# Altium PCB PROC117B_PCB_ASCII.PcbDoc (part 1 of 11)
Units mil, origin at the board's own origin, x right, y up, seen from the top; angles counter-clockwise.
Board outline 2480.32 x 3185.25 mil, 8 copper layers (Top Layer, L2_GND1, L3_SIG1, L4_PWR1, L5_PWR2, L6_SIG2, L7_GND2, Bottom Layer), stack 57.4 mil thick; 456 components, 292 nets, 7831 pads, 2905 vias.
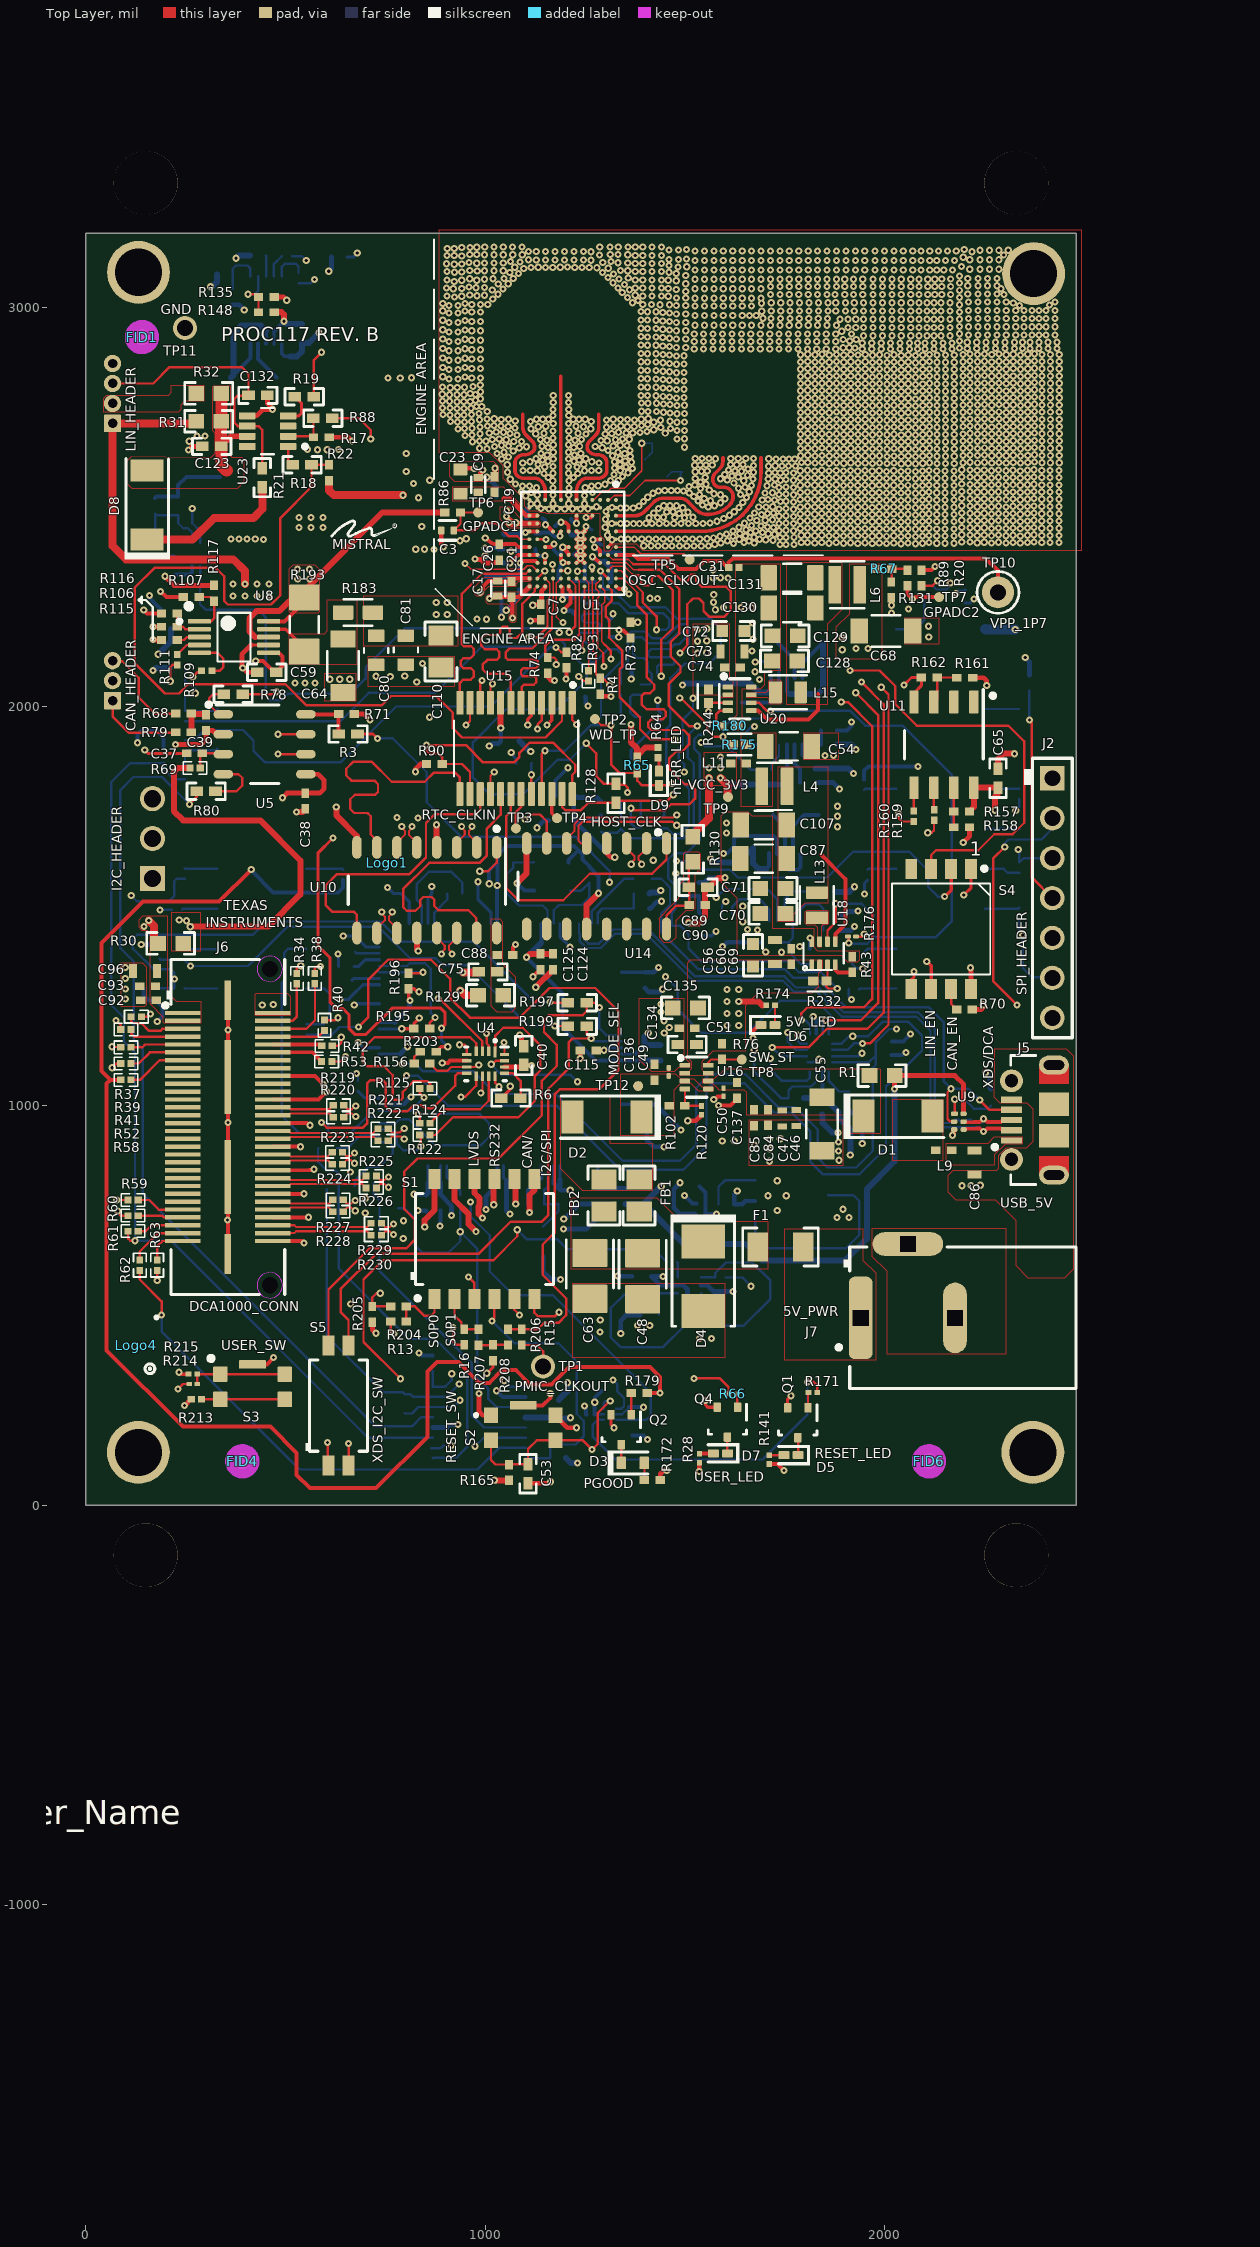
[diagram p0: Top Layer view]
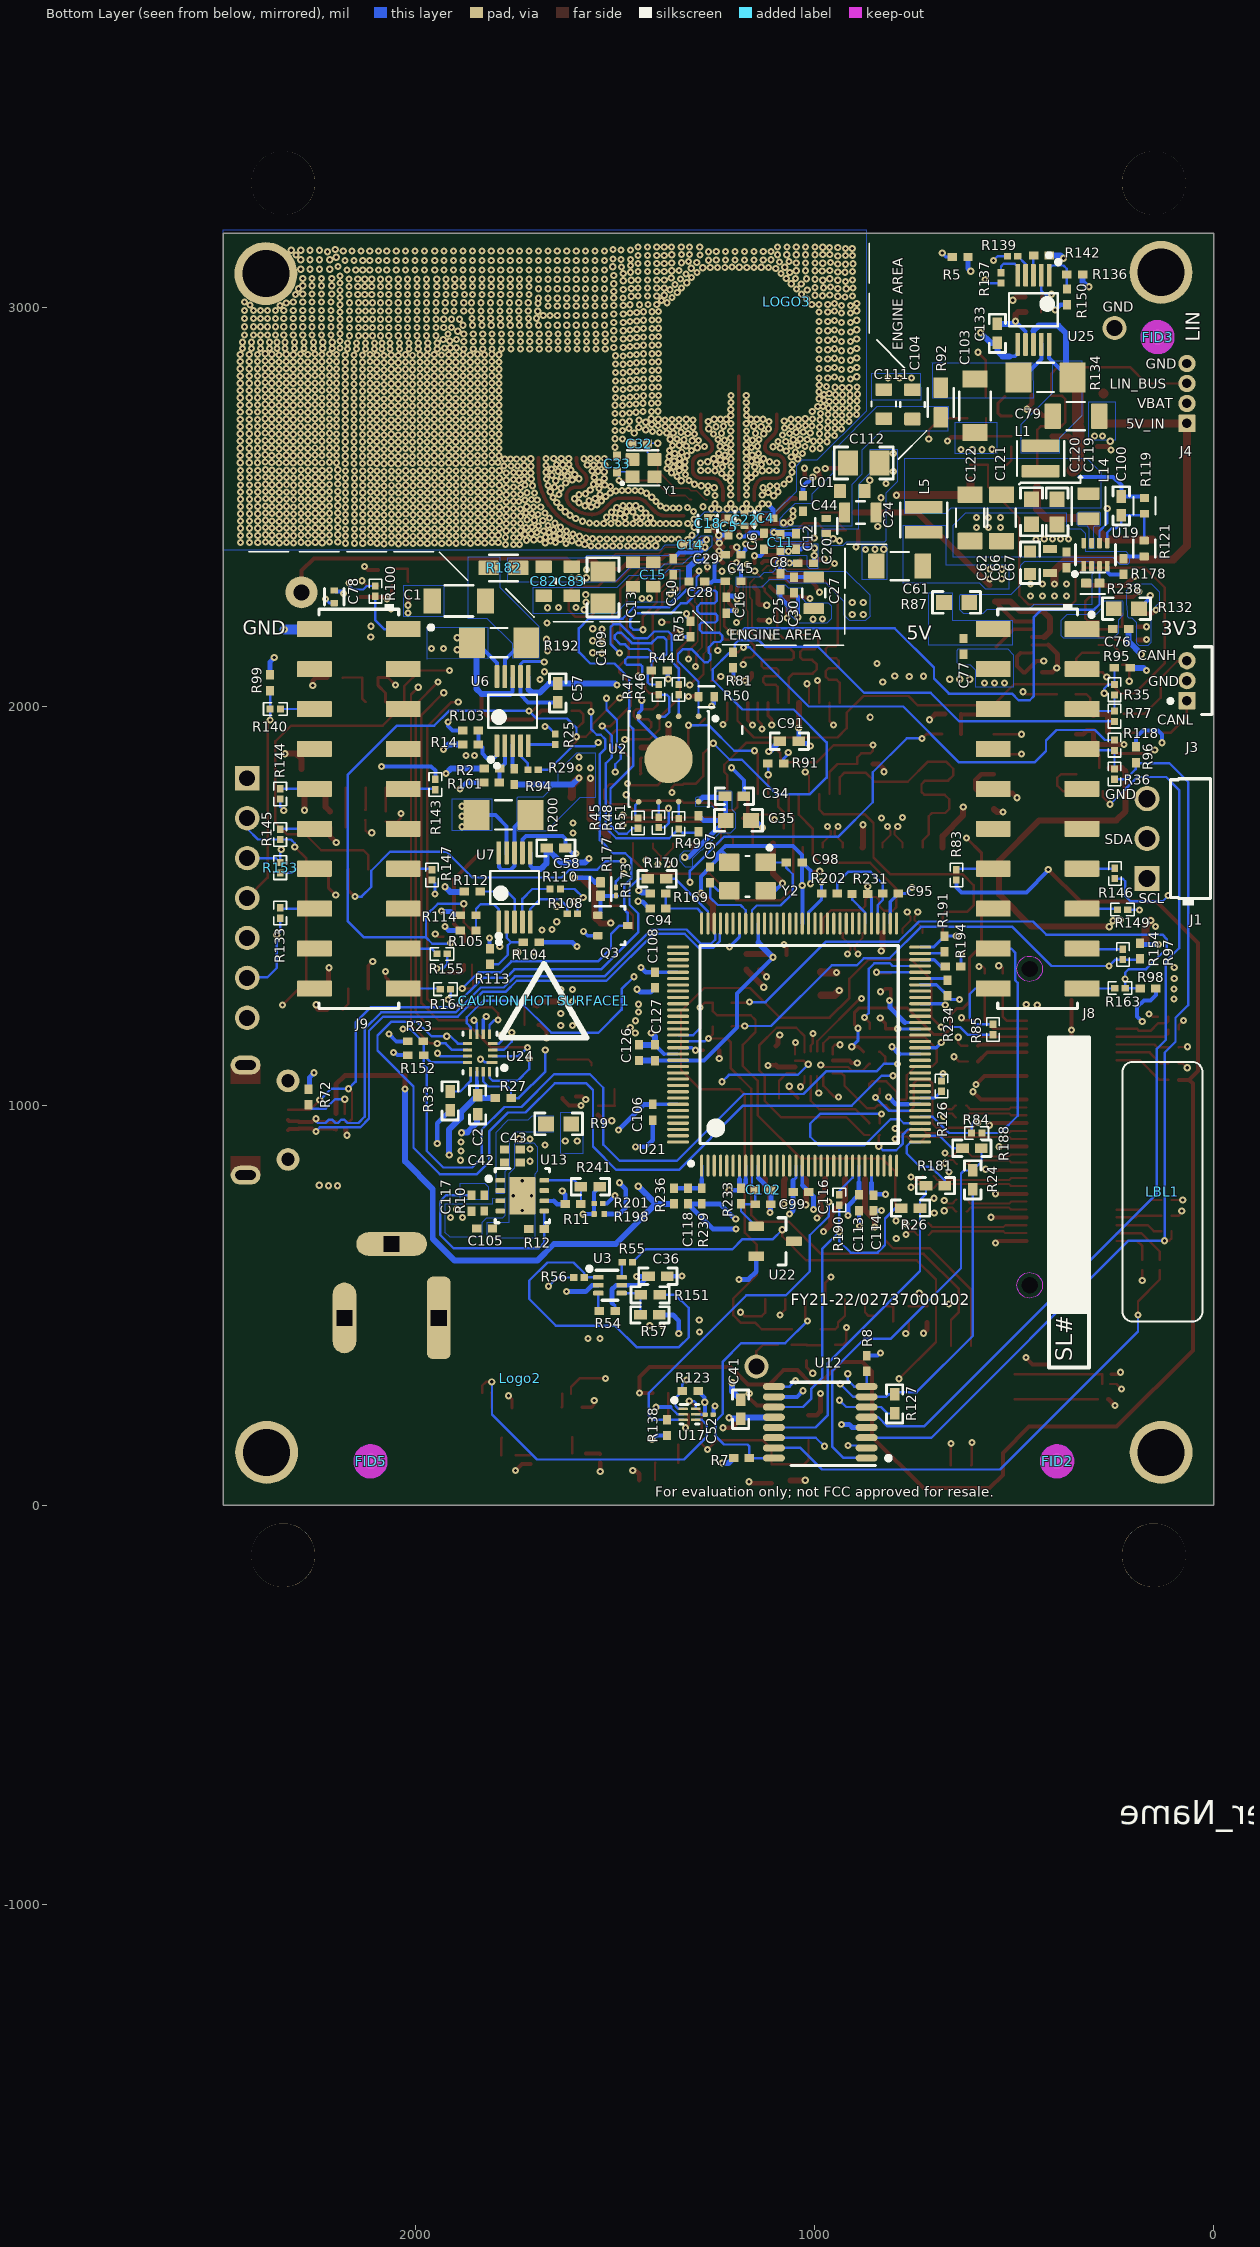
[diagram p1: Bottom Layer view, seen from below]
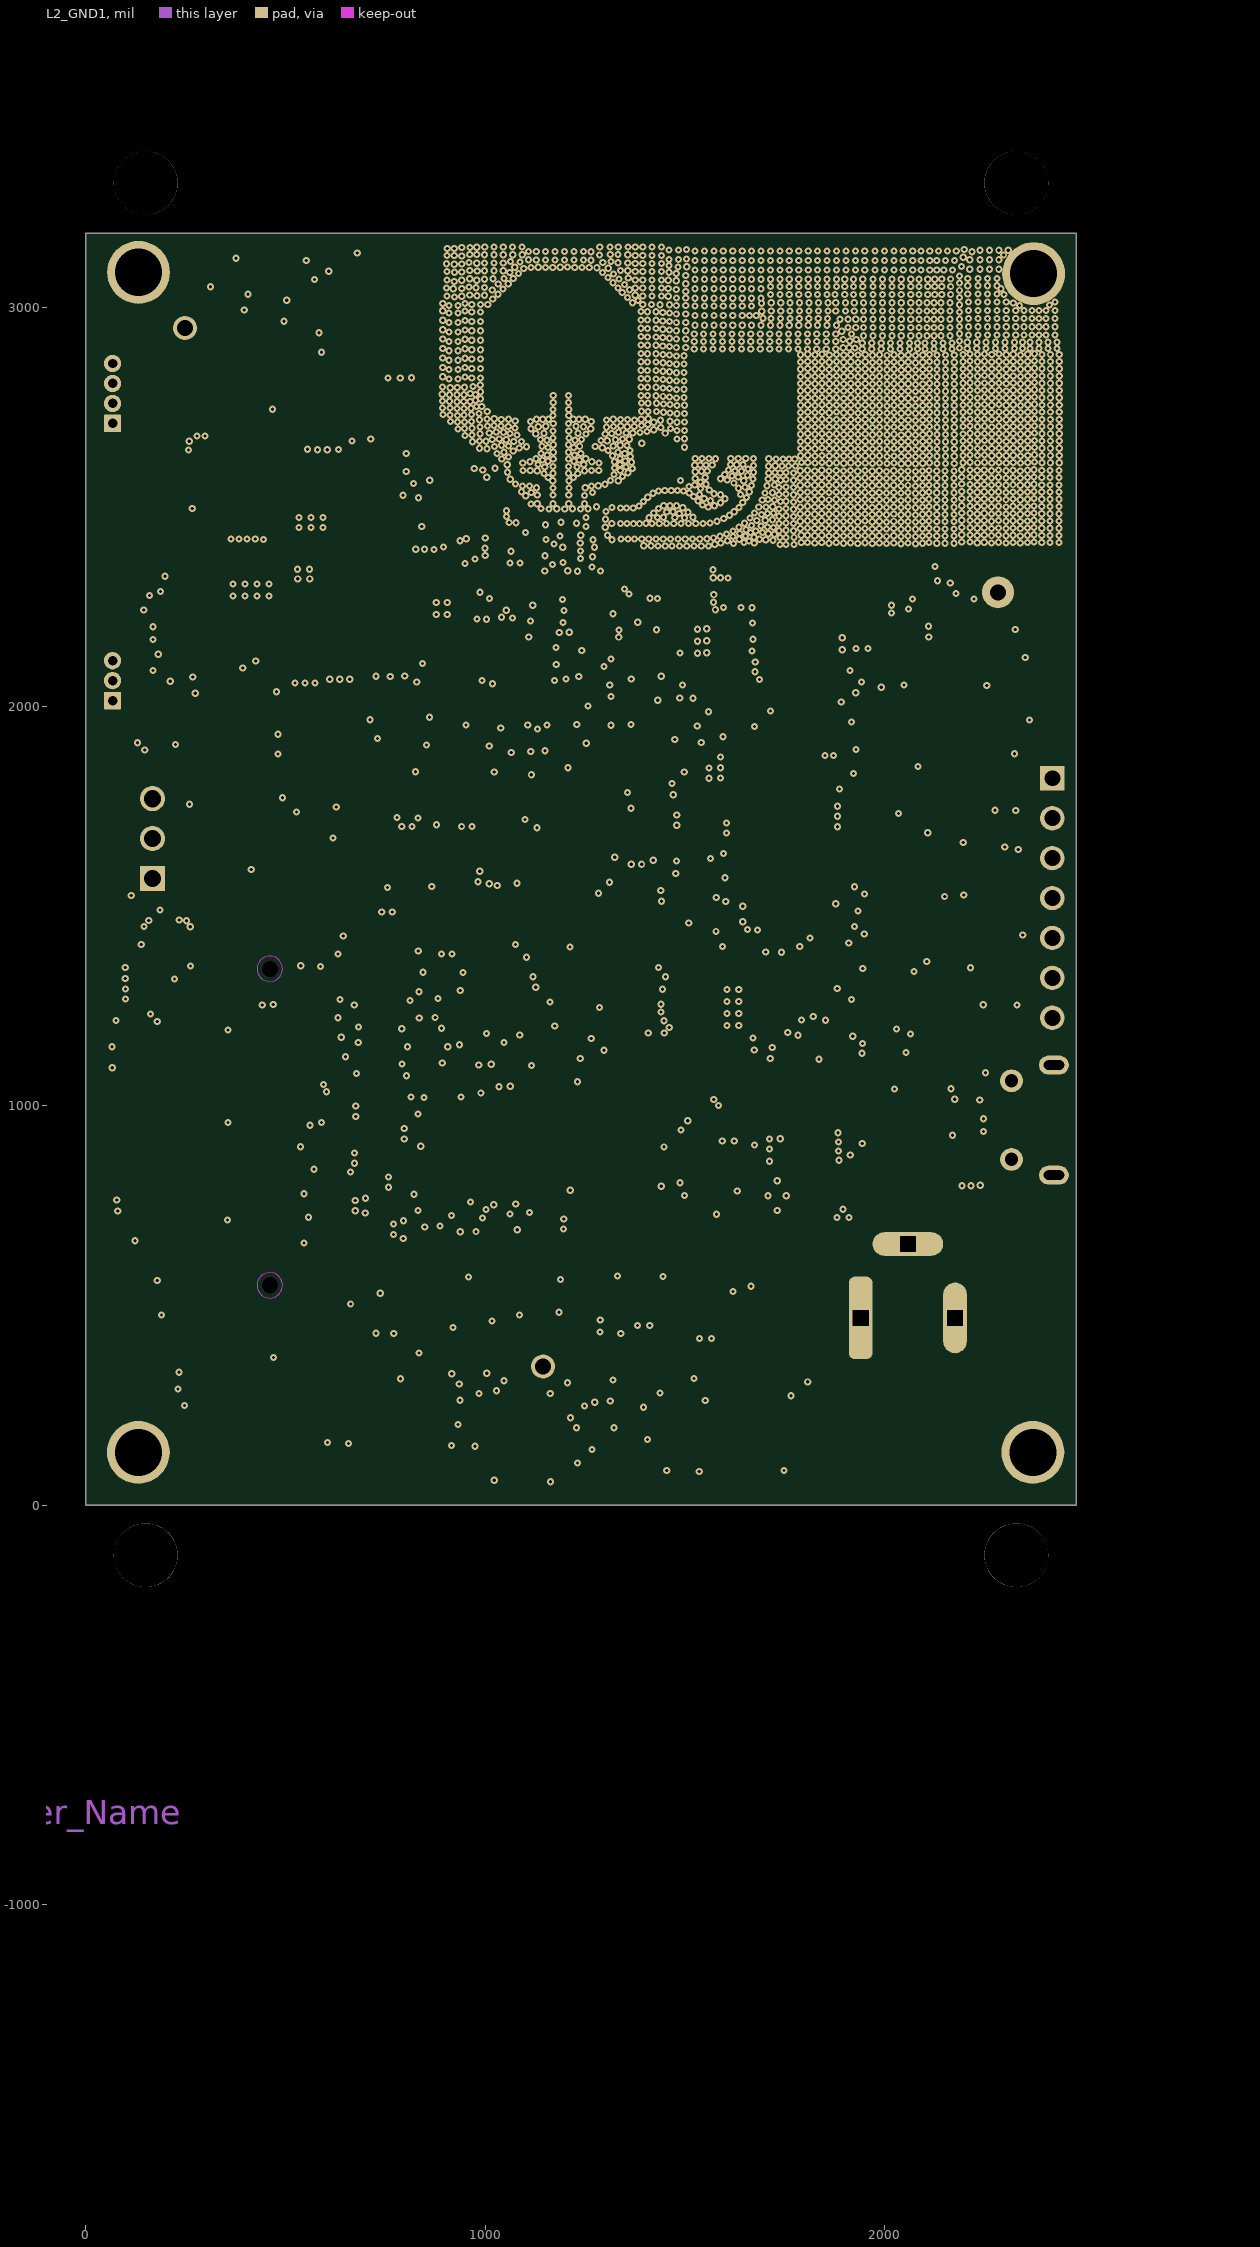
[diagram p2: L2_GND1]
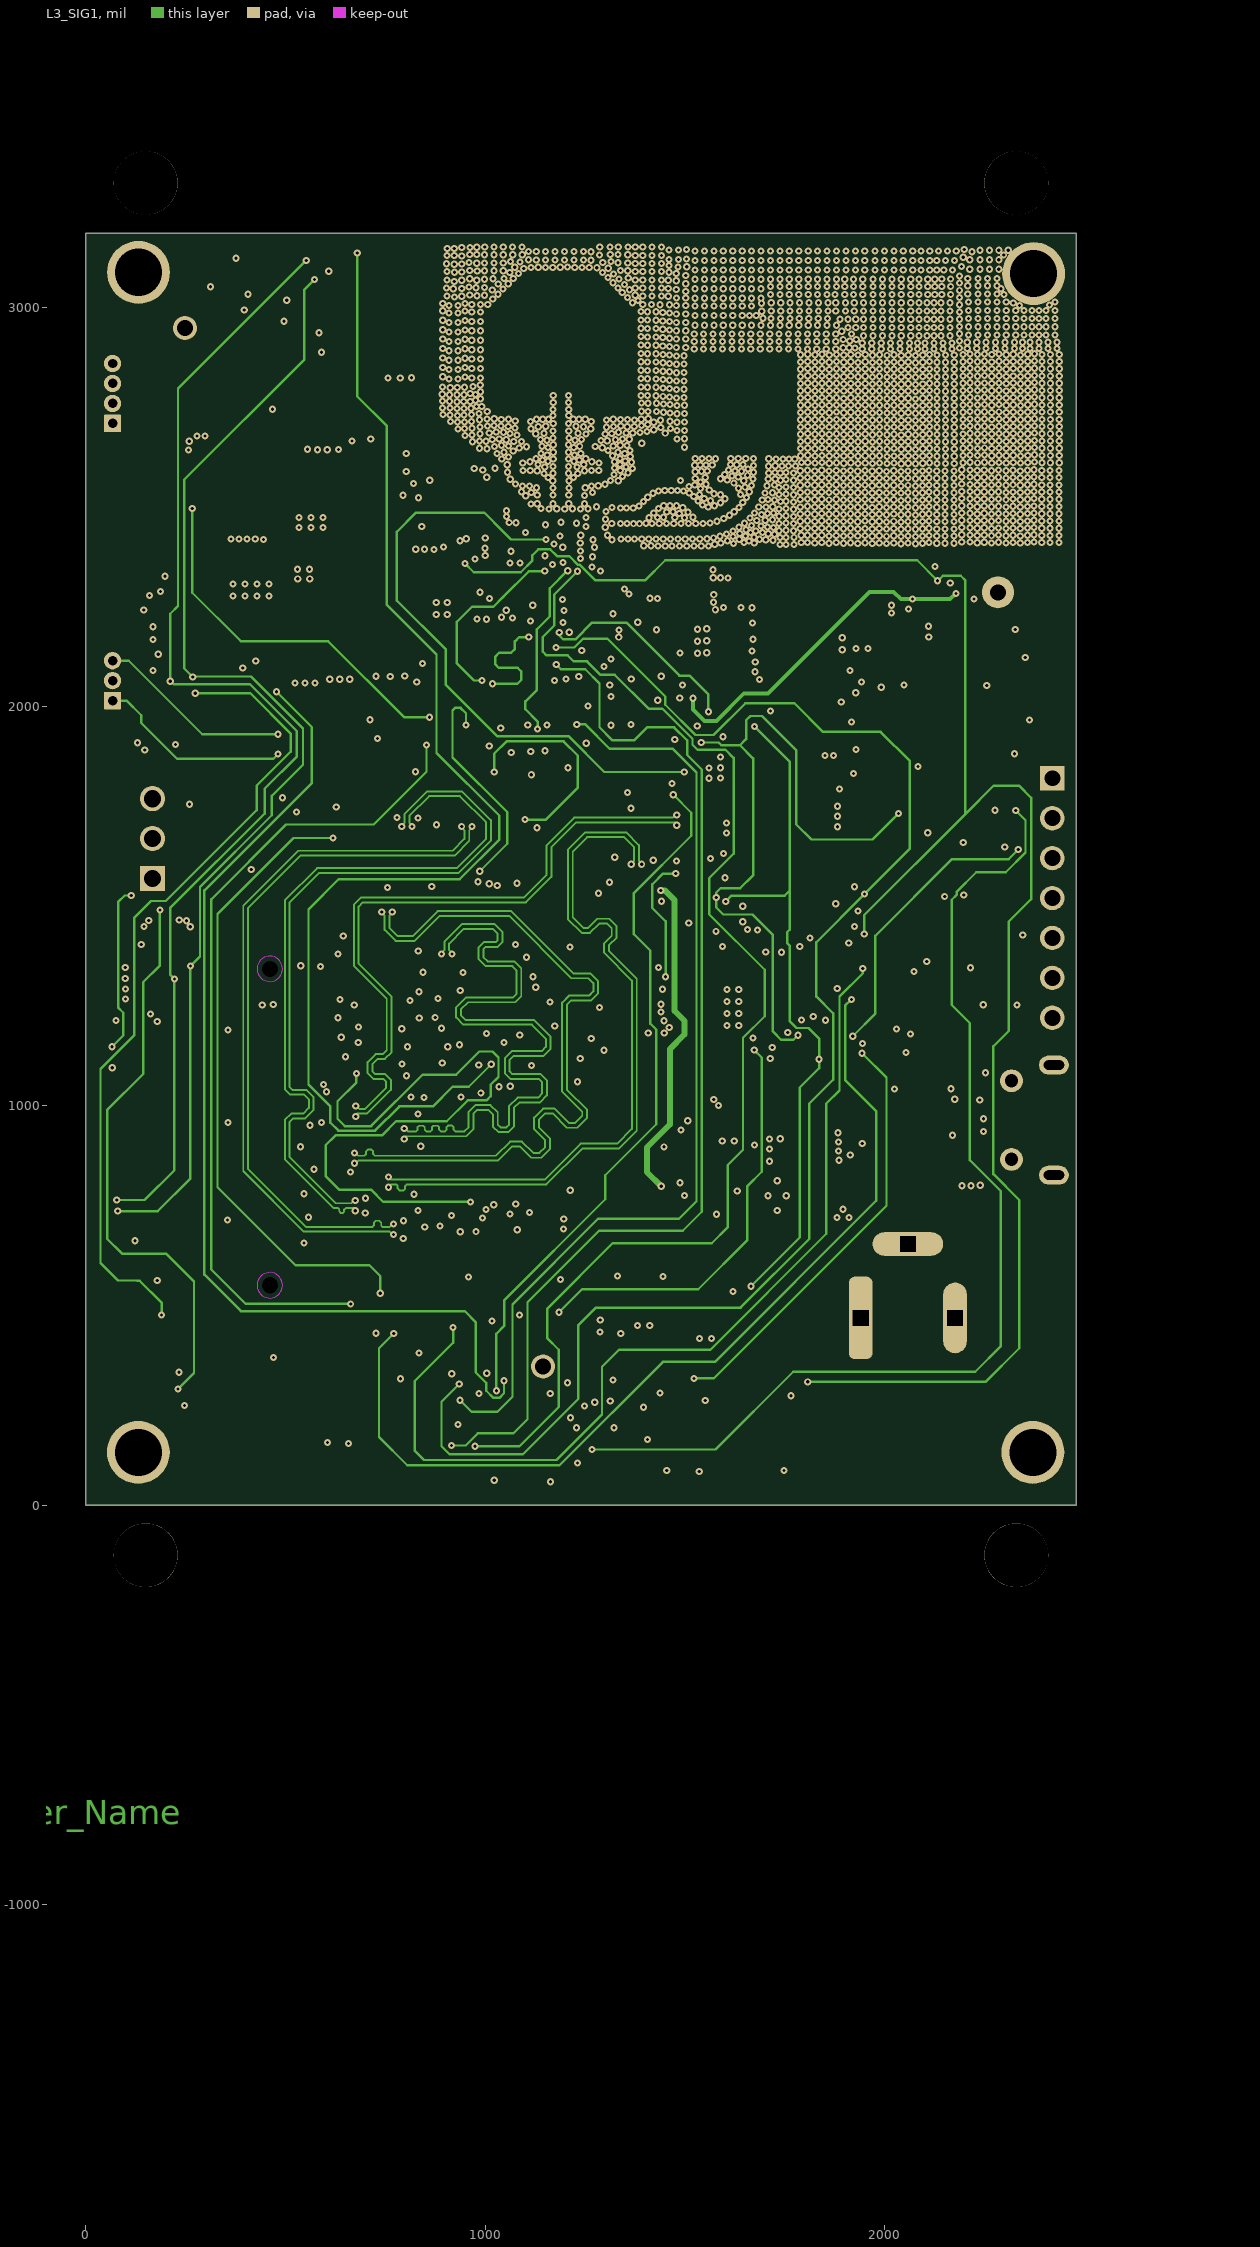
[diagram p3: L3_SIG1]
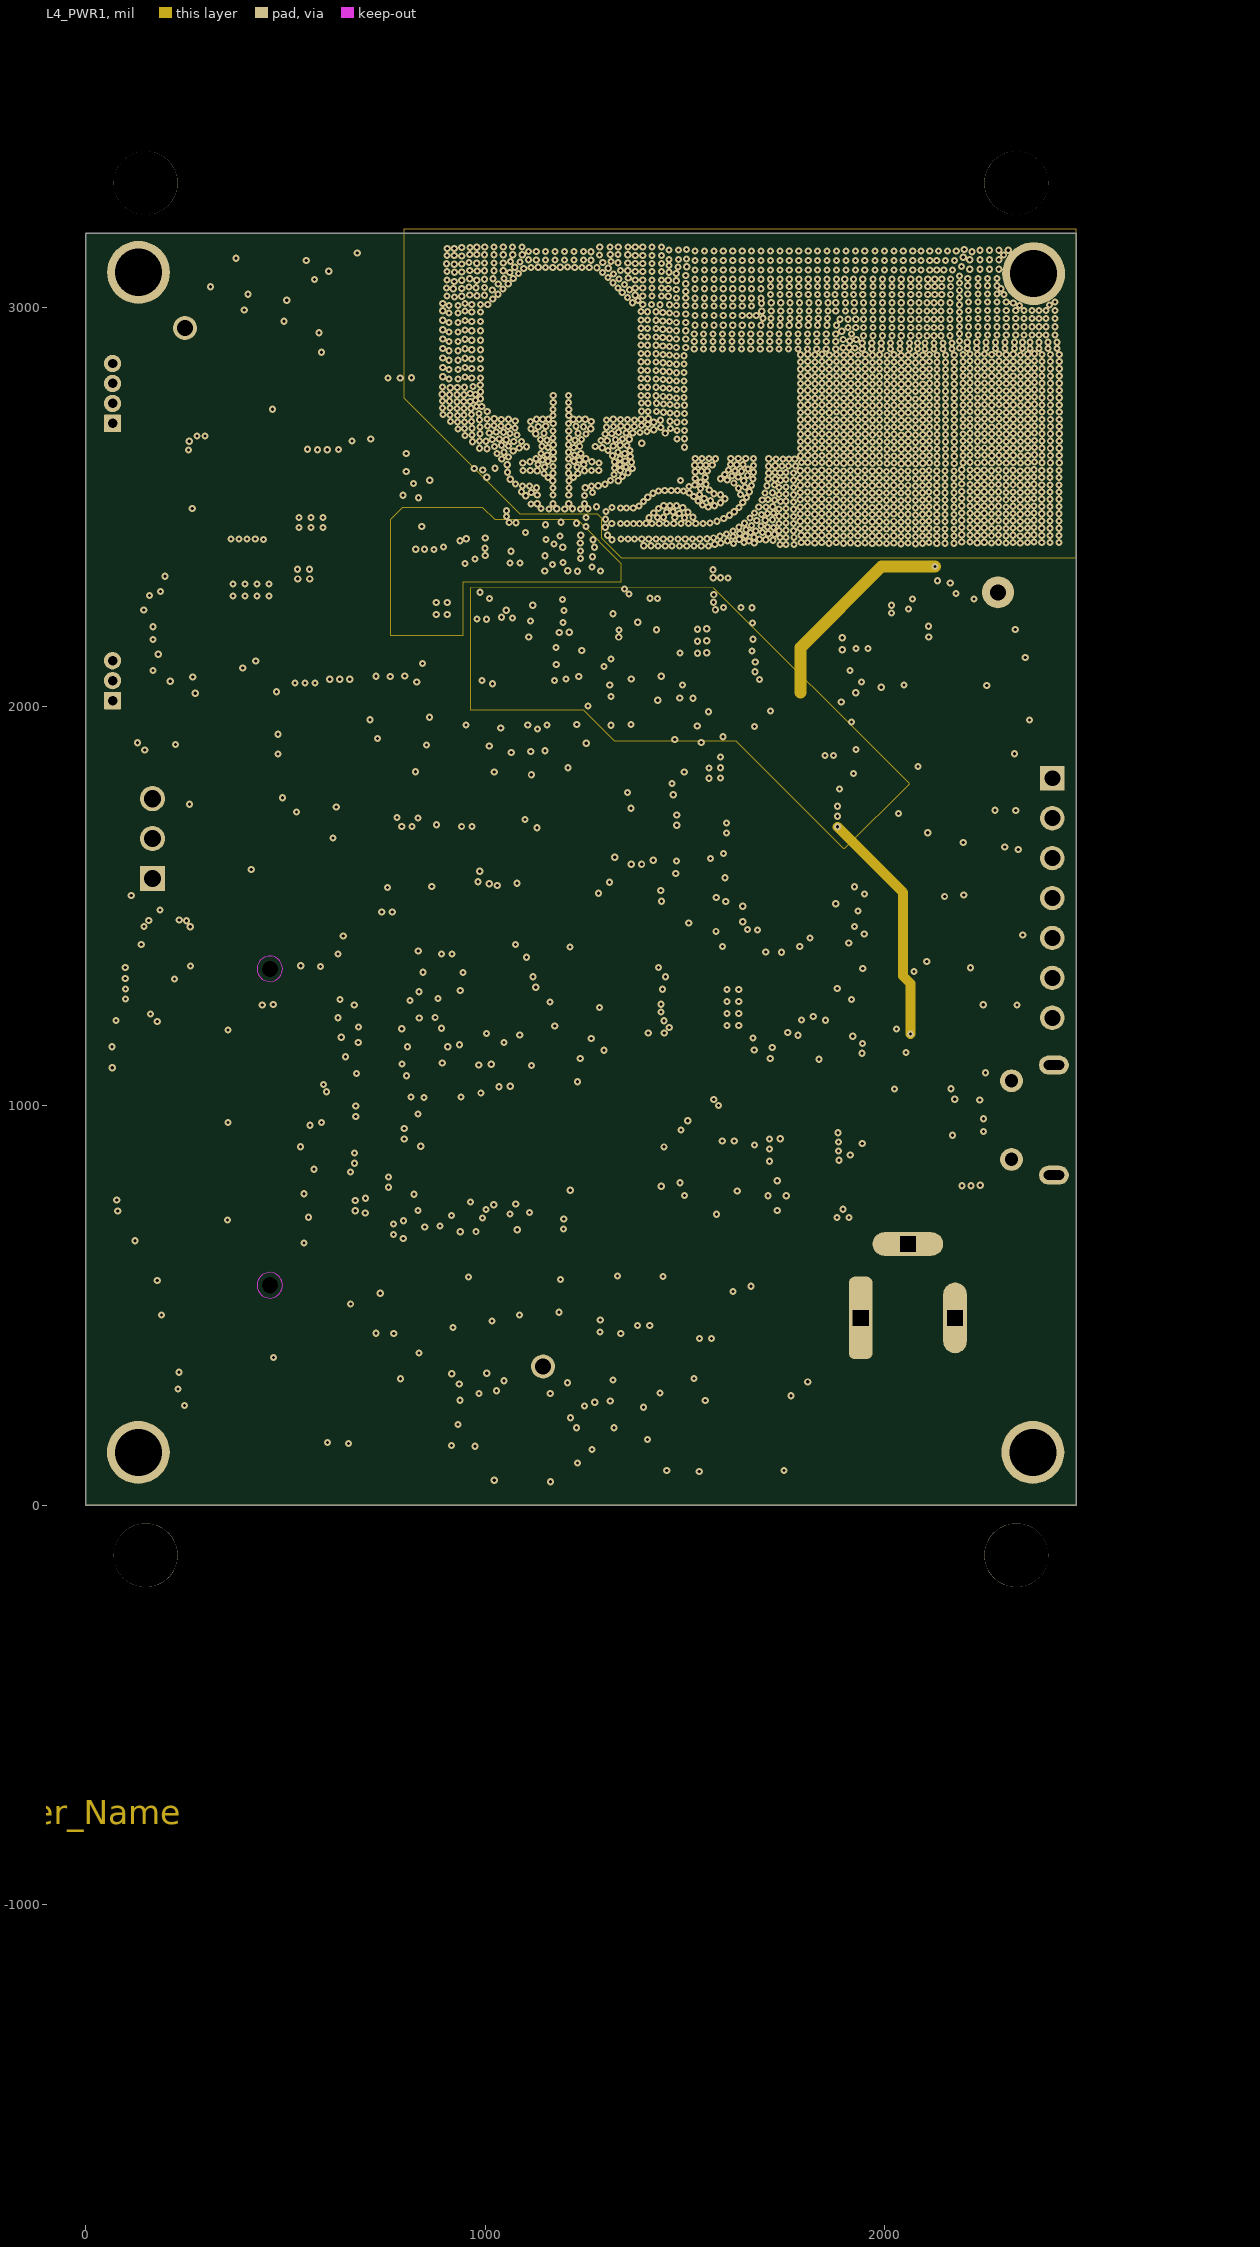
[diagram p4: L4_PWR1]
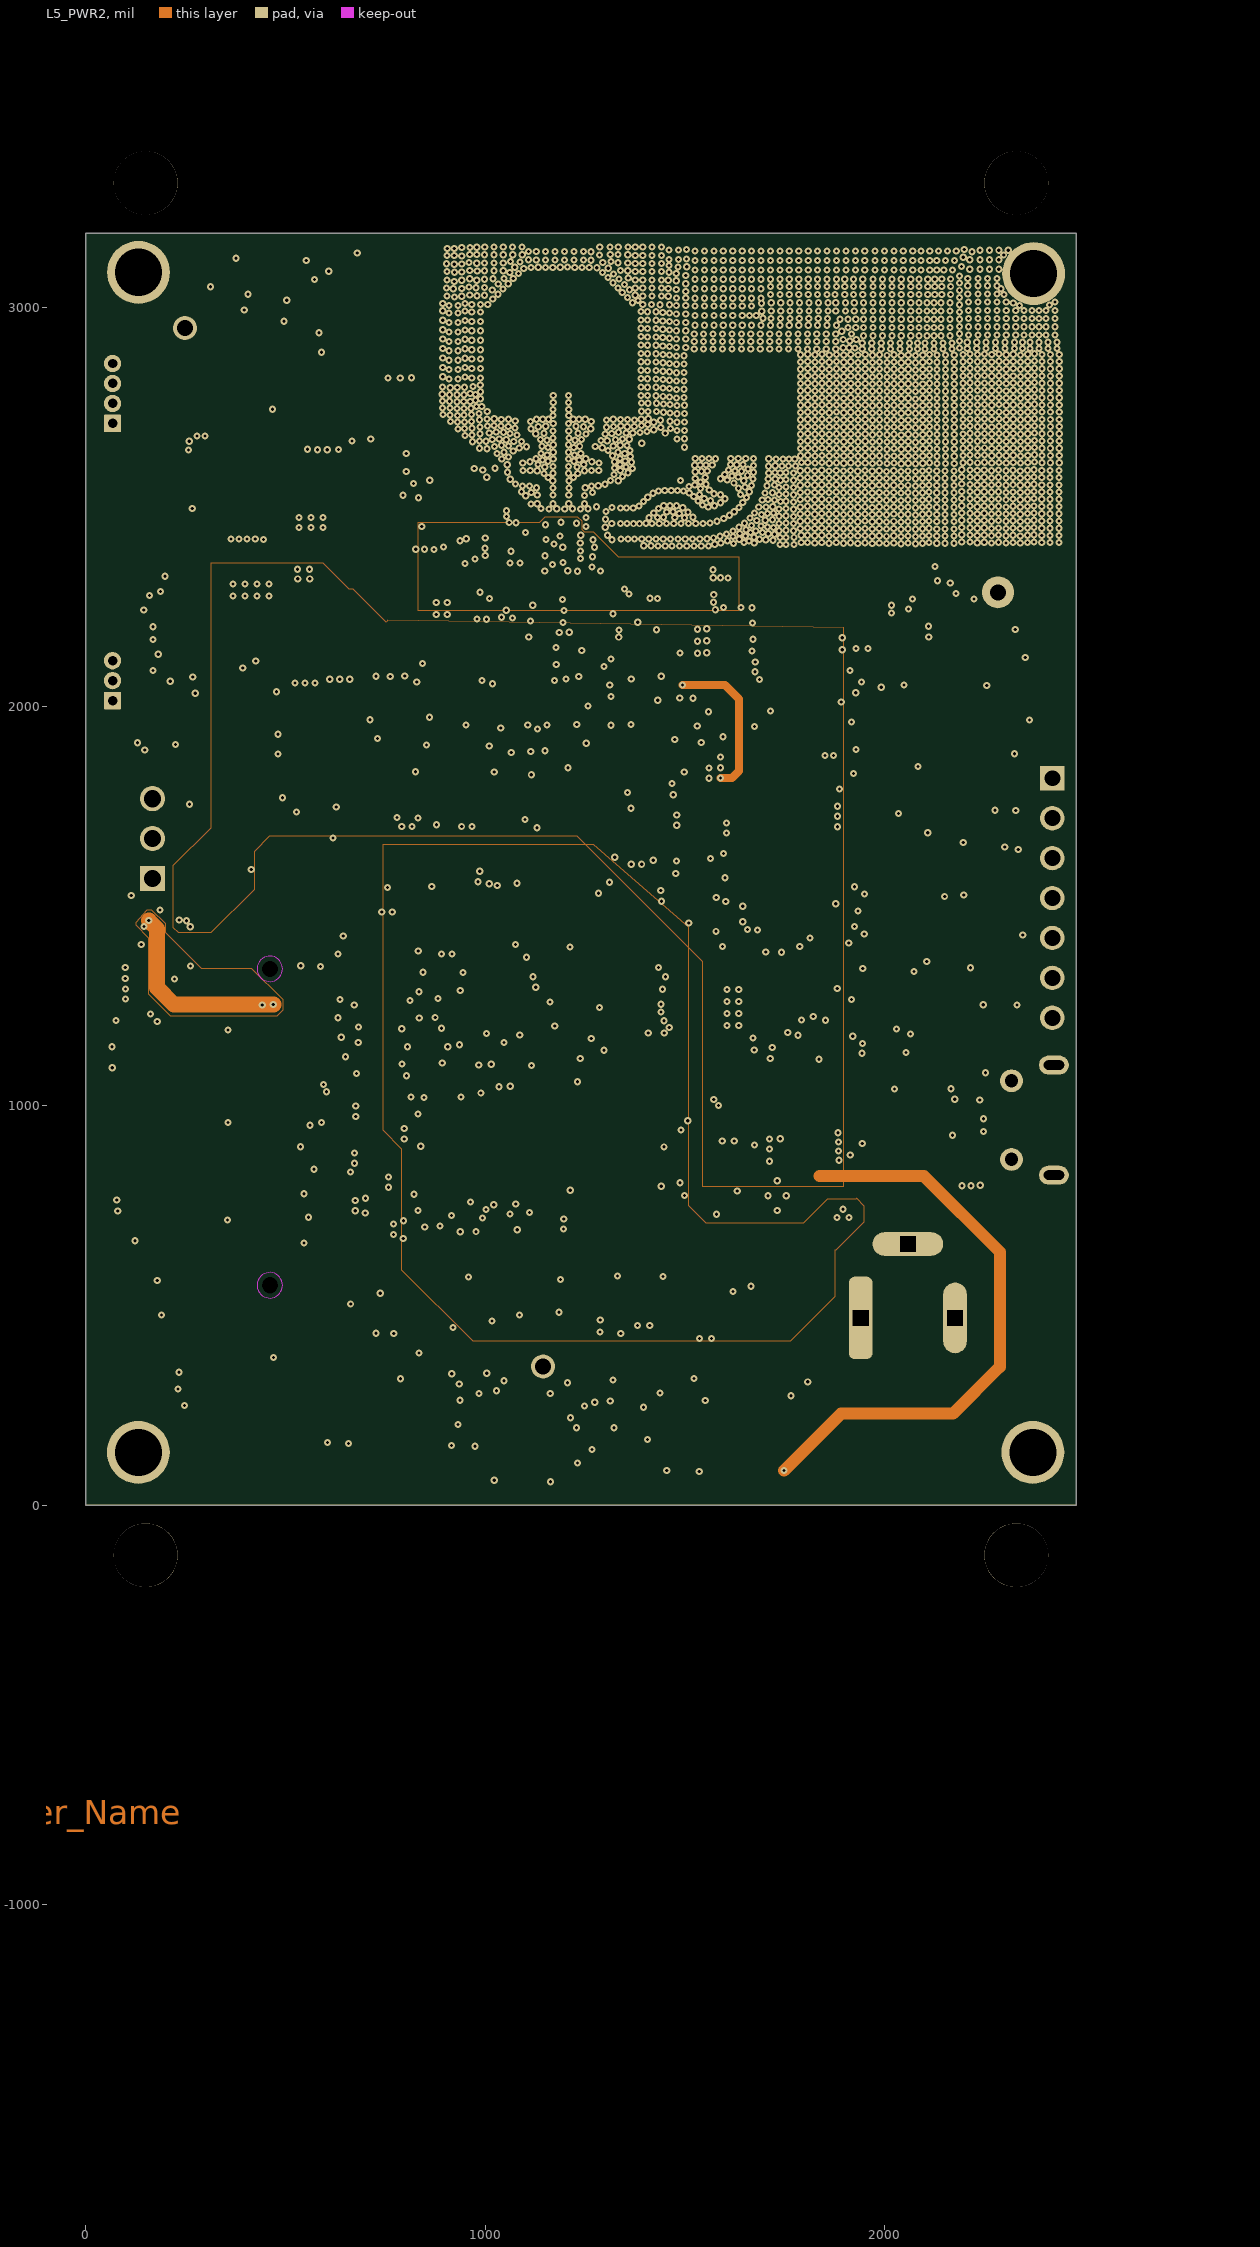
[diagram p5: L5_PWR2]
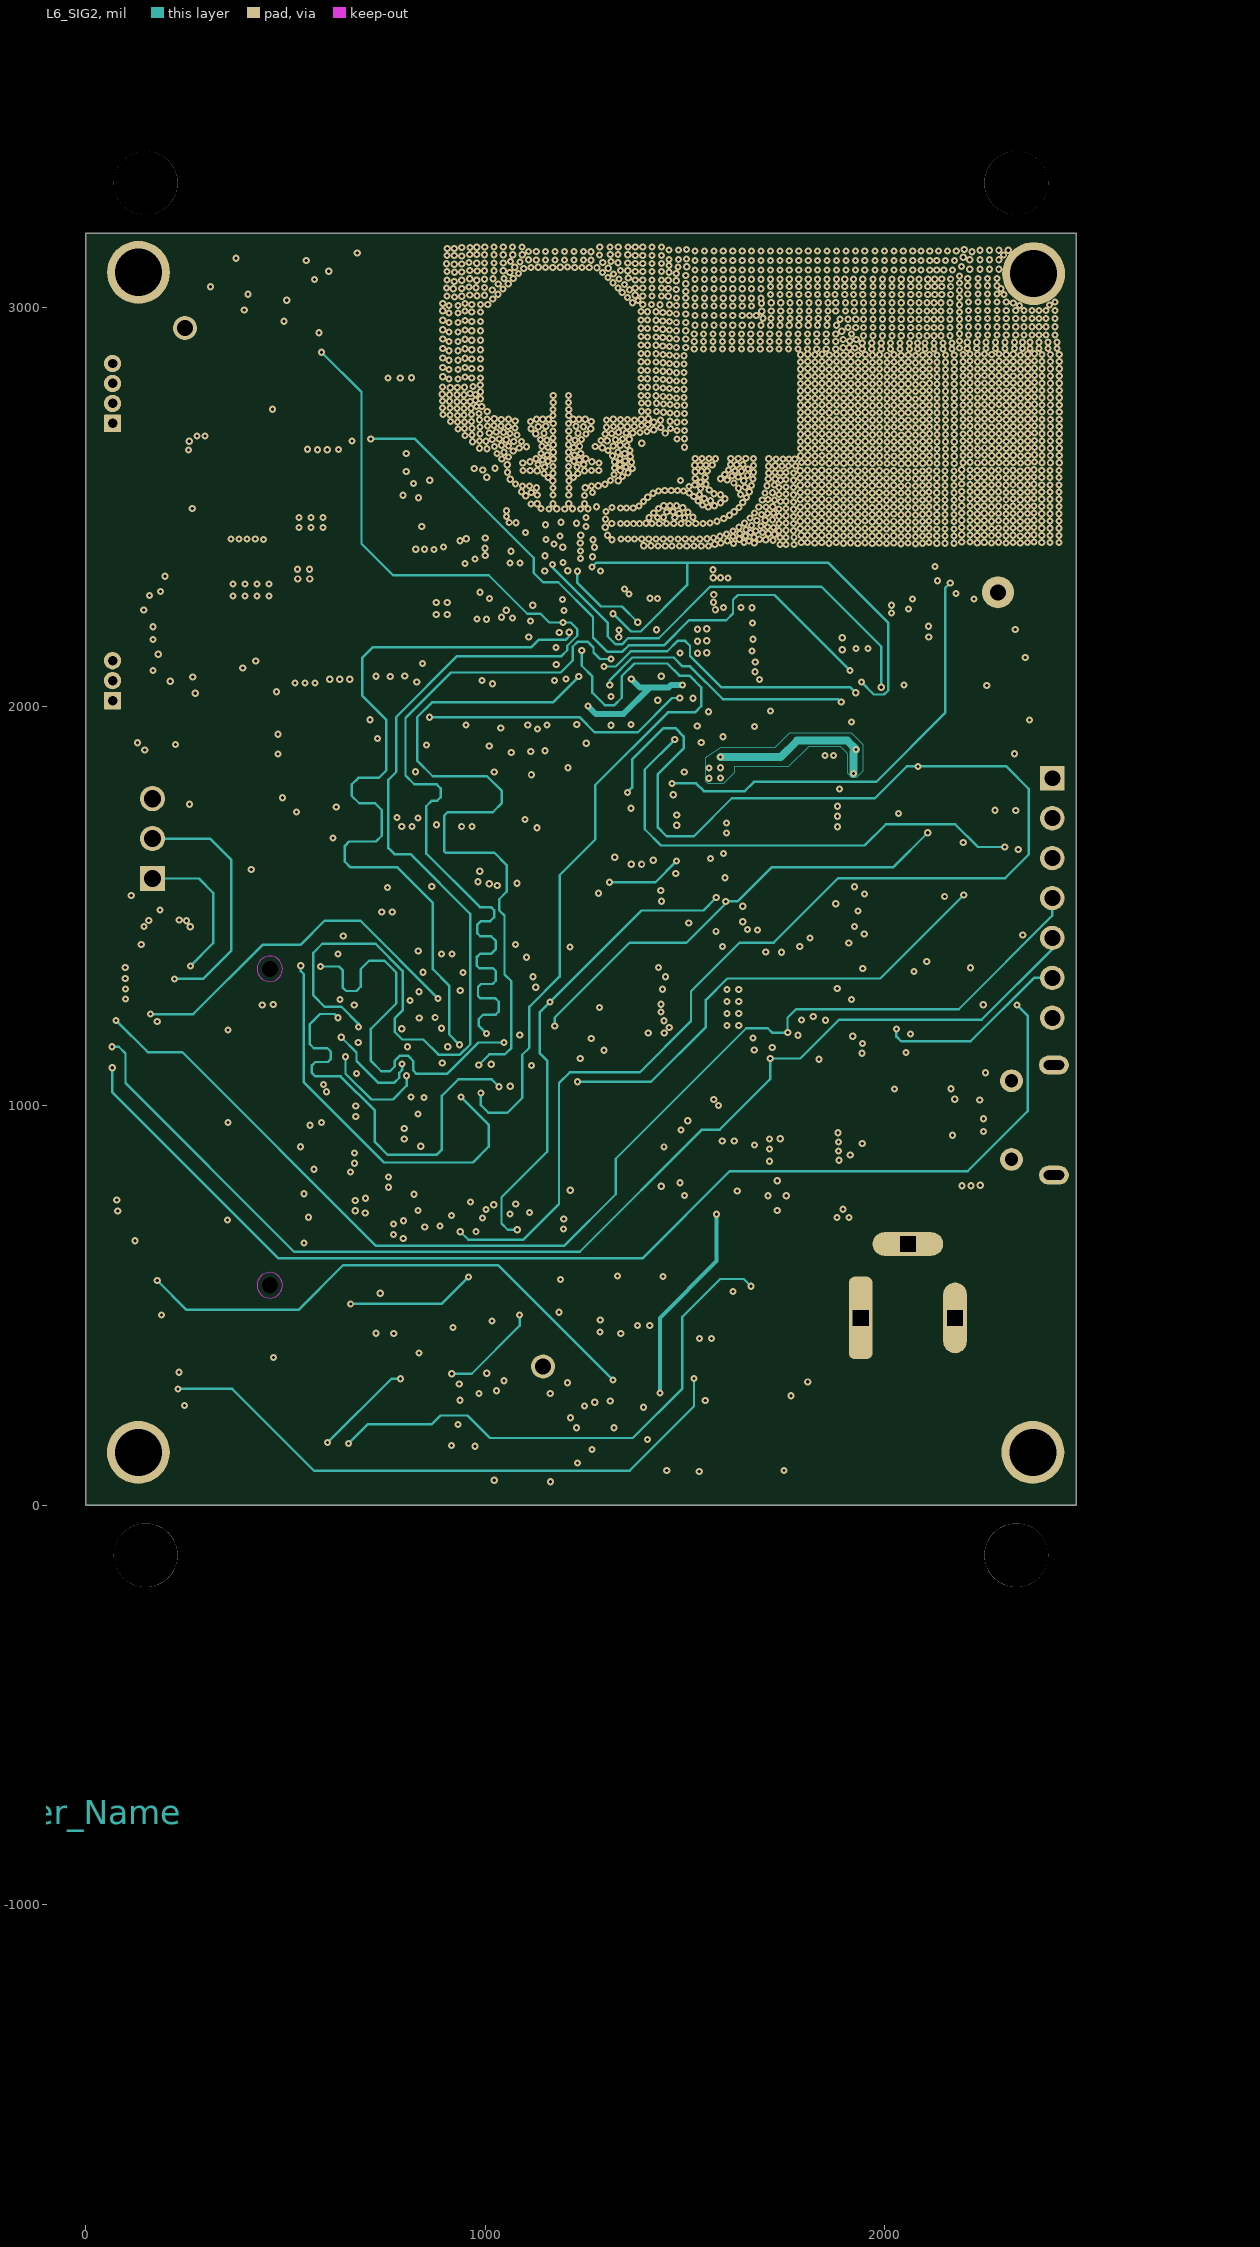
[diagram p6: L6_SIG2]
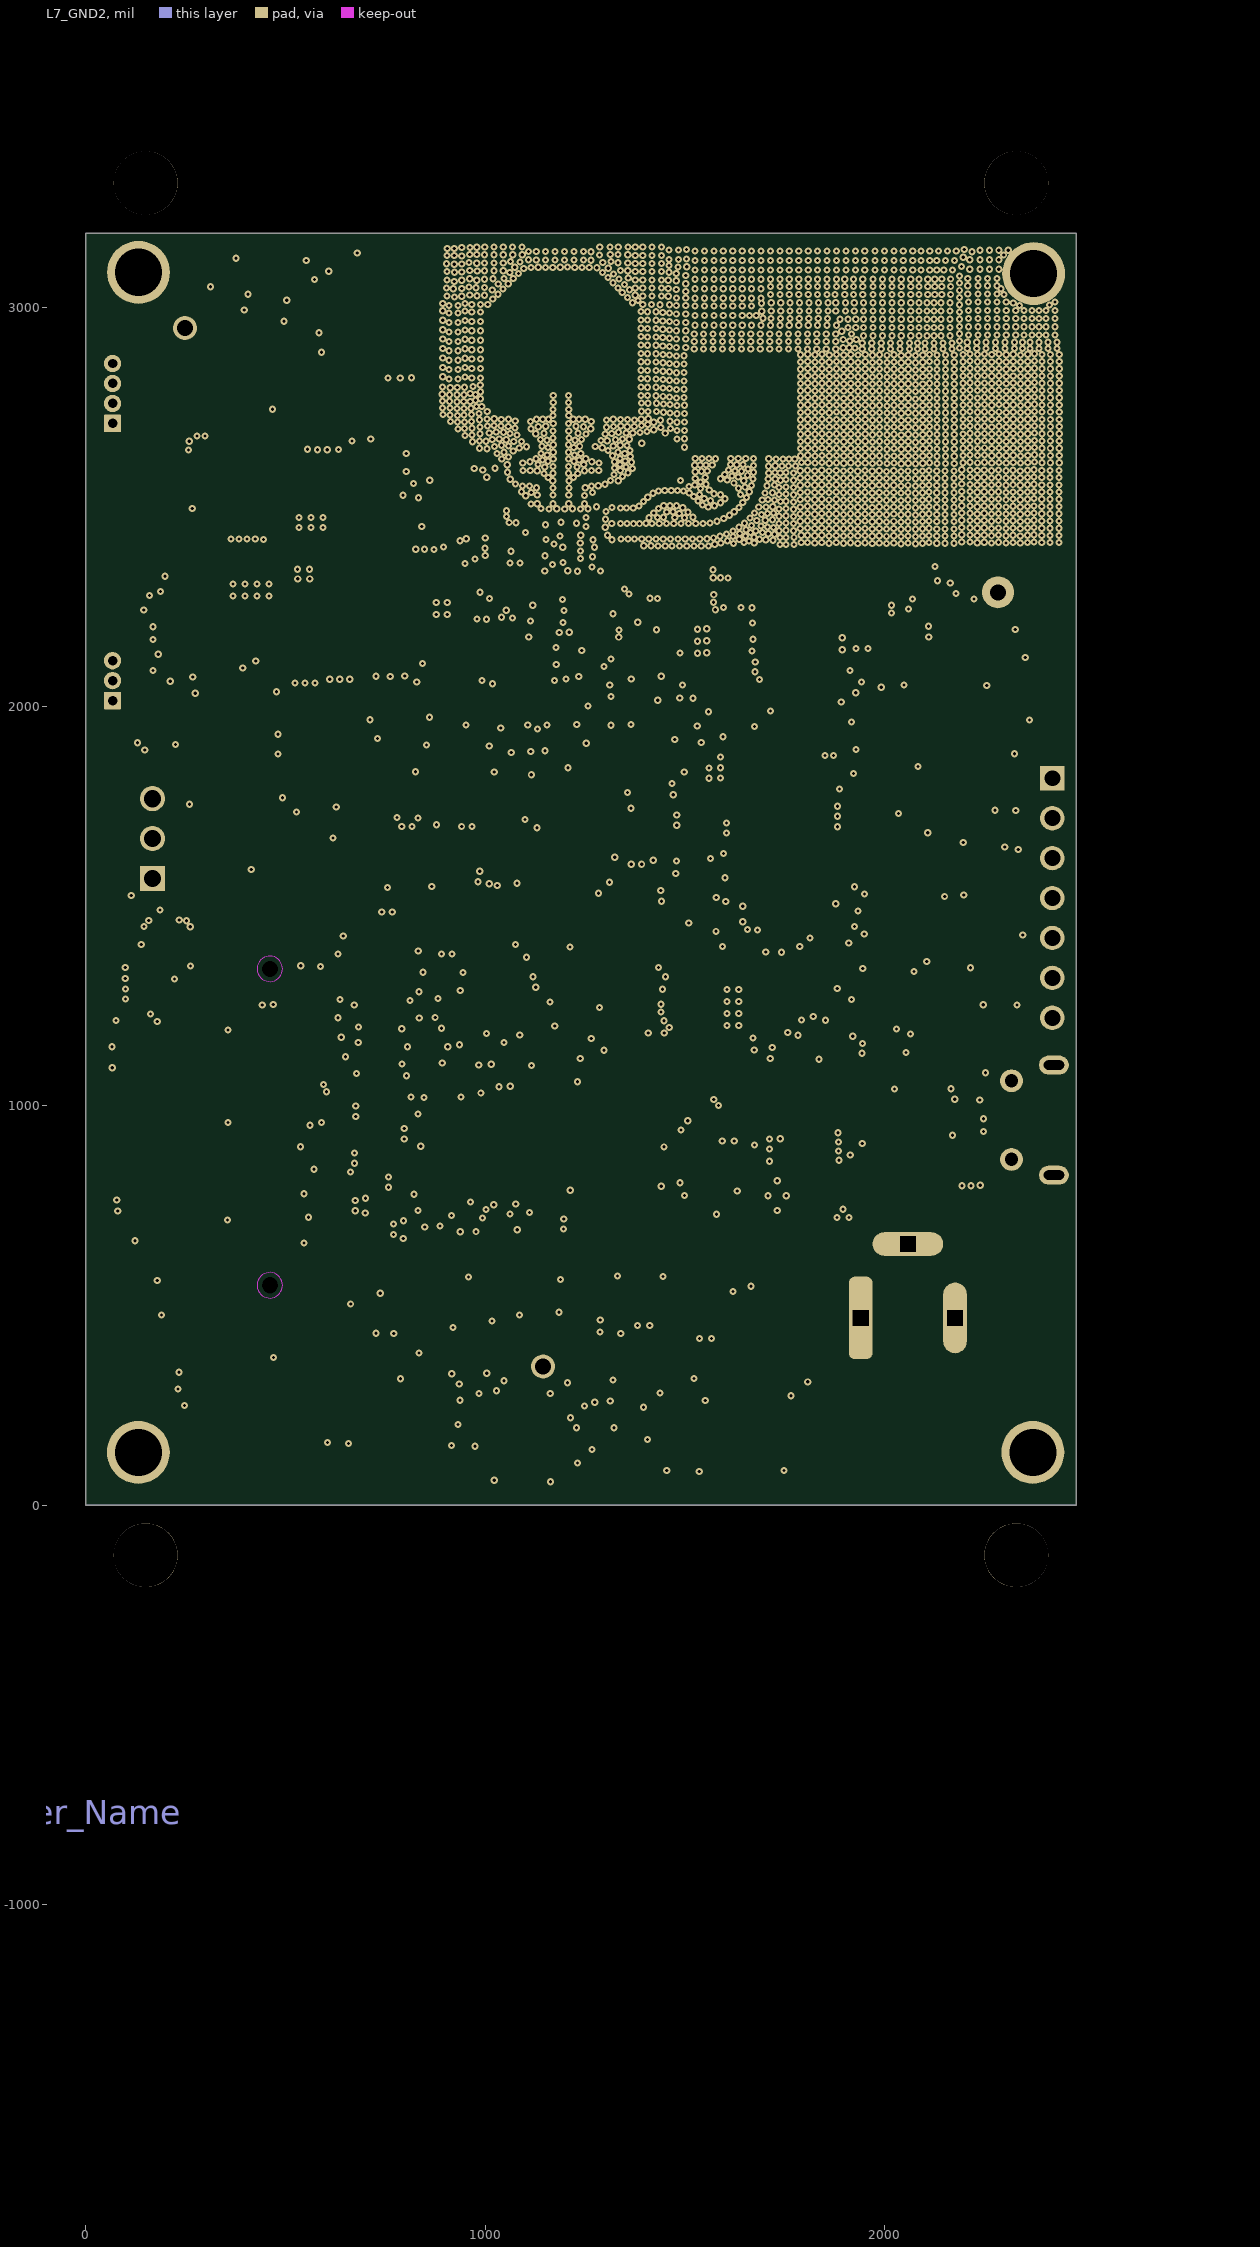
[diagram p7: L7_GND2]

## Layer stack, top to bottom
Top Solder: solder mask 0.8, Solder Resist, Dk 1
Top Layer: signal copper 1.6
Dielectric 1: core 5, Isola FR408HR (DUAL PLY, 2x1067, SPREAD GLASS ), Dk 3.3
L2_GND1: signal copper 1.2
Dielectric 2: prepreg 5.85, PCL370HR, Dk 3.9
L3_SIG1: signal copper 1.2
Dielectric 3: core 10, PCL370HR, Dk 4.25
L4_PWR1: signal copper 1.2
Dielectric 4: prepreg 5.65, PCL370HR, Dk 3.9
L5_PWR2: signal copper 1.2
Dielectric 5: prepreg 10, PCL370HR, Dk 4.25
L6_SIG2: signal copper 1.2
Dielectric 6: core 5.5, PCL370HR, Dk 3.9
L7_GND2: signal copper 1.2
Dielectric 7: core 5, PCL370HR, Dk 4.25
Bottom Layer: signal copper 1.6
Bottom Solder: solder mask 0.8, Solder Resist, Dk 1

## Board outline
0,0 0,3185.25 2480.32,3185.25 2480.32,0

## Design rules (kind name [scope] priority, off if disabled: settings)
AcuteAngle [All] p0 off: scope1count=1 scope1_0_kind=Board scope1_0_value=Board scope2count=1 scope2_0_kind=Board scope2_0_value=Board commentlength=0 minimum=4.50000000000000E+0001
AcuteAngle [All] p1 off: minimum=4.50000000000000E+0001 checktracksonly=FALSE
AssemblyTestPointUsage [All] p0: scope1count=1 scope1_0_kind=Board scope1_0_value=Board scope2count=1 scope2_0_kind=Board scope2_0_value=Board commentlength=0
AssemblyTestPointUsage [All] p1: valid=2
AssemblyTestpoint [All] p0: scope1count=1 scope1_0_kind=Board scope1_0_value=Board scope2count=1 scope2_0_kind=Board scope2_0_value=Board commentlength=0
BoardOutlineClearance [All] p0: scope1count=1 scope1_0_kind=Board scope1_0_value=Board scope2count=1 scope2_0_kind=Board scope2_0_value=Board commentlength=0 gap=12
BoardOutlineClearance [All] p1: gap=12 ignorepadtopadclearanceinfootprint=FALSE
Clearance "top and bottom" [All] p0 off: scope1count=1 scope1_0_kind=Board scope1_0_value=Board scope2count=1 scope2_0_kind=Board scope2_0_value=Board commentlength=66 gap=6 // Protel DXP Scope 1 Expression Was: OnTopLayer or OnBottomLayer
Clearance "Inner layers" [All] p0 off: scope1count=1 scope1_0_kind=Board scope1_0_value=Board scope2count=1 scope2_0_kind=Net scope2_0_value=GND commentlength=80 gap=6 // Protel DXP Scope 1 Expression Was: OnLayer('L3_SIGNAL 1') OR ('L6_SIGNAL 4')
Clearance Clearance_Keepout [All] p0 off: scope1count=1 scope1_0_kind=Board scope1_0_value=Board scope2count=1 scope2_0_kind=Board scope2_0_value=Board commentlength=48 gap=0 // Protel DXP Scope 1 Expression Was: IsKeepOut
Clearance Same_net [All] p0: scope1count=1 scope1_0_kind=Board scope1_0_value=Board scope2count=1 scope2_0_kind=Board scope2_0_value=Board commentlength=0 gap=0
Clearance Clearance_KO-J5 [All] p0 off: scope1count=1 scope1_0_kind=Board scope1_0_value=Board scope2count=1 scope2_0_kind=Component scope2_0_value=J5 commentlength=60 gap=19.6 // Protel DXP Scope 1 Expression Was: IsKeepOut and IsTrack
Clearance "Clearance_TX and RX" [All] p0: scope1count=1 scope1_0_kind=NetClass scope1_0_value="TX and RX" scope2count=1 scope2_0_kind=Board scope2_0_value=Board commentlength=0 gap=8
Clearance Clearance_BGA [All] p0 off: scope1count=1 scope1_0_kind=Board scope1_0_value=Board scope2count=1 scope2_0_kind=Board scope2_0_value=Board commentlength=57 gap=4 // Protel DXP Scope 1 Expression Was: WithinRoom('BGA1')
Clearance [All] p0: scope1count=1 scope1_0_kind=Board scope1_0_value=Board scope2count=1 scope2_0_kind=Board scope2_0_value=Board commentlength=0 gap=6
Clearance Clearance_Keepout [IsKeepOut] p1: gap=0 ignorepadtopadclearanceinfootprint=TRUE
Clearance "Clearance_TX and RX" [InNetClass('TX and RX')] p2: gap=8 ignorepadtopadclearanceinfootprint=FALSE except(0: Text-Hole; 4: Arc-Text Track-Text SMDPad-Text THPad-Text Via-Text Fill-Text Poly-Text Region-Text Text-Text; 5.3: Arc-Via Arc-Fill Arc-Poly Arc-Region Track-Via Track-Fill Track-Poly Track-Region Poly-Region; 6: Arc-Hole Track-Hole SMDPad-Via SMDPad-Hole THPad-Hole Via-Hole; 7.7: Fill-Fill Fill-Poly Fill-Region Poly-Poly Region-Region; 9: SMDPad-SMDPad; 10: Arc-SMDPad Arc-THPad Track-SMDPad Track-THPad SMDPad-THPad THPad-THPad THPad-Via; 11: Fill-Hole Poly-Hole Region-Hole)
Clearance Clearance_BGA [WithinRoom('BGA1')] p3: gap=4 ignorepadtopadclearanceinfootprint=FALSE except(8: Fill-Fill Fill-Poly Fill-Region Poly-Poly Poly-Region Region-Region; 10: Fill-Hole Poly-Hole Region-Hole)
Clearance "top and bottom" [OnTopLayer or OnBottomLayer] p4: gap=6 ignorepadtopadclearanceinfootprint=TRUE except(5: Arc-Arc Arc-Track Arc-SMDPad Arc-Hole Track-Track Track-SMDPad Track-Hole SMDPad-Hole THPad-Hole Via-Hole Text-Hole; 5.1: SMDPad-SMDPad; 7: Arc-Fill Arc-Poly Arc-Region Track-Fill Track-Region; 8: Track-Poly SMDPad-Fill SMDPad-Poly SMDPad-Region THPad-Fill THPad-Poly THPad-Region Via-Fill Via-Poly Via-Region Poly-Poly; 10: Fill-Fill Fill-Poly Fill-Region Poly-Region Region-Region; 11: Fill-Hole Poly-Hole Region-Hole)
Clearance Clearance_KO-J5 [IsKeepOut and IsTrack vs InComponent('J5')] p5: gap=19.6 ignorepadtopadclearanceinfootprint=FALSE except(9: SMDPad-SMDPad)
Clearance "Inner layers" [OnLayer('L3_SIGNAL 1') OR ('L6_SIGNAL 4') vs InNet('GND')] p6: gap=6 ignorepadtopadclearanceinfootprint=TRUE except(0: Text-Hole; 5: Arc-Arc Arc-Track Arc-SMDPad Track-Track Track-SMDPad; 5.1: SMDPad-SMDPad; 7: Arc-Fill Arc-Poly Arc-Region Track-Fill Track-Region; 8: SMDPad-Fill SMDPad-Poly SMDPad-Region THPad-Fill THPad-Poly THPad-Region; 10: Fill-Fill Fill-Poly Fill-Region Poly-Region Region-Region; 11: Fill-Hole Poly-Hole Region-Hole; 15: Track-Poly; 20: Poly-Poly)
Clearance [All] p7: gap=6 ignorepadtopadclearanceinfootprint=TRUE except(0: Text-Hole; 5: Arc-Arc Arc-Track Arc-SMDPad Track-Track Track-SMDPad; 5.1: SMDPad-SMDPad; 7: Arc-Fill Arc-Poly Arc-Region Track-Fill Track-Region; 8: SMDPad-Fill SMDPad-Poly SMDPad-Region THPad-Fill THPad-Poly THPad-Region; 10: Fill-Fill Fill-Poly Fill-Region Poly-Region Region-Region; 11: Fill-Hole Poly-Hole Region-Hole; 12: Track-Poly; 15: Poly-Poly)
Clearance Same_net [All] p8: gap=0 ignorepadtopadclearanceinfootprint=TRUE
ComponentClearance ComponentClearance_MatingCon-3D [All] p0 off: scope1count=1 scope1_0_kind=Board scope1_0_value=Board scope2count=1 scope2_0_kind=Board scope2_0_value=Board commentlength=57 gap=0 collisioncheckmode=3 // Protel DXP Scope 2 Expression Was: not InAnyComponent
ComponentClearance "ComponentClearance_WEE Logo" [All] p0: scope1count=1 scope1_0_kind=Component scope1_0_value=Logo4 scope2count=1 scope2_0_kind=Board scope2_0_value=Board commentlength=0 gap=0 collisioncheckmode=3
ComponentClearance ComponentClearance_R77 [All] p0: scope1count=1 scope1_0_kind=Component scope1_0_value=R77 scope2count=1 scope2_0_kind=Component scope2_0_value=Logo1 commentlength=0 gap=0 collisioncheckmode=3
ComponentClearance ComponentClearance_Logo [All] p0: scope1count=1 scope1_0_kind=ComponentClass scope1_0_value=Logo scope2count=1 scope2_0_kind=Board scope2_0_value=Board commentlength=0 gap=0 collisioncheckmode=3
ComponentClearance "ComponentClearance_Mounting Holes_Fiducial Marks" [All] p0: scope1count=1 scope1_0_kind=ComponentClass scope1_0_value=FiducialMark scope2count=1 scope2_0_kind=PadClass scope2_0_value="Mounting Holes PADS" commentlength=0 gap=50 collisioncheckmode=3
ComponentClearance [All] p0: scope1count=1 scope1_0_kind=Board scope1_0_value=Board scope2count=1 scope2_0_kind=Board scope2_0_value=Board commentlength=0 gap=6 collisioncheckmode=3
ComponentClearance ComponentClearance_MatingCon-3D [All vs not InAnyComponent] p1: gap=0 collisioncheckmode=3 verticalgap=0 showdistances=FALSE
ComponentClearance "ComponentClearance_WEE Logo" [InComponent('Logo4')] p2: gap=0 collisioncheckmode=3 verticalgap=0 showdistances=TRUE
ComponentClearance ComponentClearance_R77 [InComponent('R77') vs InComponent('Logo1')] p3: gap=0 collisioncheckmode=3 verticalgap=0 showdistances=TRUE
ComponentClearance ComponentClearance_Logo [InComponentClass('Logo')] p4: gap=0 collisioncheckmode=3 verticalgap=0 showdistances=TRUE
ComponentClearance "ComponentClearance_Mounting Holes_Fiducial Marks" [InComponentClass('FiducialMark') vs InPadClass('Mounting Holes PADS')] p5: gap=50 collisioncheckmode=3 verticalgap=10 showdistances=TRUE
ComponentClearance [All] p6: gap=6 collisioncheckmode=3 verticalgap=10 showdistances=TRUE
DiffPairsRouting 90E [All] p0 off: scope1count=1 scope1_0_kind=Board scope1_0_value=Board scope2count=1 scope2_0_kind=Board scope2_0_value=Board commentlength=69 // Protel DXP Scope 1 Expression Was: InDifferentialPairClass('90E')
DiffPairsRouting 100E [All] p0 off: scope1count=1 scope1_0_kind=Board scope1_0_value=Board scope2count=1 scope2_0_kind=Board scope2_0_value=Board commentlength=70 // Protel DXP Scope 1 Expression Was: InDifferentialPairClass('100E')
DiffPairsRouting 100E [InDifferentialPairClass('100E')] p1: maxlimit=7.2 minlimit=5 mostfreqgap=7.2 toplayer_maxgap=5 toplayer_prefgap=5 toplayer_minwidth=5.2 toplayer_maxwidth=5.2 toplayer_prefwidth=5.2 midlayer1_mingap=7.2 midlayer1_minwidth=4.8 midlayer1_maxwidth=4.8 midlayer1_prefwidth=4.8 midlayer2_mingap=7.2 midlayer2_minwidth=4.8 midlayer2_maxwidth=4.8 midlayer2_prefwidth=4.8 midlayer3_mingap=7.2 midlayer3_minwidth=4.8 midlayer3_maxwidth=4.8 midlayer3_prefwidth=4.8 midlayer4_mingap=7.2 midlayer4_minwidth=4.8 midlayer4_maxwidth=4.8 midlayer4_prefwidth=4.8 midlayer5_mingap=7.2 midlayer5_minwidth=4.8 midlayer5_maxwidth=4.8 midlayer5_prefwidth=4.8 midlayer6_mingap=7.2 midlayer6_minwidth=4.8 midlayer6_maxwidth=4.8 midlayer6_prefwidth=4.8 bottomlayer_maxgap=5 bottomlayer_prefgap=5 bottomlayer_minwidth=5.2 bottomlayer_maxwidth=5.2 bottomlayer_prefwidth=5.2 maxuncoupledlength=500
DiffPairsRouting 90E [InDifferentialPairClass('90E')] p2: maxlimit=7.2 minlimit=5 mostfreqgap=7.2 toplayer_mingap=7 toplayer_maxgap=7 toplayer_prefgap=7 toplayer_minwidth=9.42 toplayer_maxwidth=9.42 toplayer_prefwidth=9.42 midlayer1_mingap=7.2 midlayer1_minwidth=4.8 midlayer1_maxwidth=4.8 midlayer1_prefwidth=4.8 midlayer2_mingap=7 midlayer2_maxgap=7 midlayer2_prefgap=7 midlayer2_minwidth=5.4 midlayer2_maxwidth=5.4 midlayer2_prefwidth=5.4 midlayer3_mingap=7.2 midlayer3_minwidth=4.8 midlayer3_maxwidth=4.8 midlayer3_prefwidth=4.8 midlayer4_mingap=7.2 midlayer4_minwidth=4.8 midlayer4_maxwidth=4.8 midlayer4_prefwidth=4.8 midlayer5_mingap=7.2 midlayer5_minwidth=4.8 midlayer5_maxwidth=4.8 midlayer5_prefwidth=4.8 midlayer6_mingap=7 midlayer6_maxgap=7 midlayer6_prefgap=7 midlayer6_minwidth=5.4 midlayer6_maxwidth=5.4 midlayer6_prefwidth=5.4 bottomlayer_maxgap=5 bottomlayer_prefgap=5 bottomlayer_minwidth=6 bottomlayer_maxwidth=6 bottomlayer_prefwidth=6 maxuncoupledlength=500
FabricationTestPointUsage TestPointUsage [All] p0: scope1count=1 scope1_0_kind=Board scope1_0_value=Board scope2count=1 scope2_0_kind=Board scope2_0_value=Board commentlength=0 valid=2 allowmultiple=FALSE
FabricationTestPointUsage TestPointUsage [All] p1: valid=2 allowmultiple=FALSE
FabricationTestpoint Testpoint [All] p0: scope1count=1 scope1_0_kind=Board scope1_0_value=Board scope2count=1 scope2_0_kind=Board scope2_0_value=Board commentlength=0 side=3 testpointundercomponent=TRUE minsize=40 maxsize=100 preferedsize=60 minholesize=0 maxholesize=40 preferedholesize=32 testpointgrid=1
FabricationTestpoint Testpoint [All] p1: side=3 testpointundercomponent=TRUE minsize=40 maxsize=100 preferedsize=60 minholesize=0 maxholesize=40 preferedholesize=32 testpointgrid=1 allowsidetop=TRUE allowsidebottom=TRUE usegrid=TRUE gridtolerance=0.01
FanoutControl Fanout_LCC [All] p0 off: scope1count=1 scope1_0_kind=Board scope1_0_value=Board scope2count=1 scope2_0_kind=Board scope2_0_value=Board commentlength=69 // Protel DXP Scope 1 Expression Was: IsLCC   Fanout_LCC (Default Rule)
FanoutControl Fanout_BGA [All] p0 off: scope1count=1 scope1_0_kind=Board scope1_0_value=Board scope2count=1 scope2_0_kind=Board scope2_0_value=Board commentlength=69 // Protel DXP Scope 1 Expression Was: IsBGA   Fanout_BGA (Default Rule)
FanoutControl Fanout_SOIC [All] p0 off: scope1count=1 scope1_0_kind=Board scope1_0_value=Board scope2count=1 scope2_0_kind=Board scope2_0_value=Board commentlength=71 // Protel DXP Scope 1 Expression Was: IsSOIC   Fanout_SOIC (Default Rule)
FanoutControl Fanout_Default [All] p0: scope1count=1 scope1_0_kind=Board scope1_0_value=Board scope2count=1 scope2_0_kind=Board scope2_0_value=Board commentlength=30 // Fanout_Default (Default Rule)
FanoutControl Fanout_Small [All] p0 off: scope1count=1 scope1_0_kind=Board scope1_0_value=Board scope2count=1 scope2_0_kind=Board scope2_0_value=Board commentlength=84 // Protel DXP Scope 1 Expression Was: (CompPinCount < 5)   Fanout_Small (Default Rule)
FanoutControl Fanout_LCC [IsLCC] p1: bgadir=Out bgaviamode=Centered fanoutstyle=Auto fanoutdirection=Alternating viagrid=1 // Fanout_LCC (Default Rule)
FanoutControl Fanout_BGA [IsBGA] p2: bgadir=Out bgaviamode=Centered fanoutstyle=Auto fanoutdirection=Alternating viagrid=1 // Fanout_BGA (Default Rule)
FanoutControl Fanout_Default [All] p4: bgadir=Out bgaviamode=Centered fanoutstyle=Auto fanoutdirection=Alternating viagrid=1 // Fanout_Default (Default Rule)
FanoutControl Fanout_Small [(CompPinCount < 5)] p5: bgadir=Out bgaviamode=Centered fanoutstyle=Auto fanoutdirection=OutThenIn viagrid=1 // Fanout_Small (Default Rule)
Height Room_Hieght [All] p0 off: scope1count=1 scope1_0_kind=Board scope1_0_value=Board scope2count=1 scope2_0_kind=Board scope2_0_value=Board commentlength=69 // Protel DXP Scope 1 Expression Was: WithinRoom('Room_Hieght 1 MM')
Height Room_Hieght [WithinRoom('Room_Hieght 1 MM')] p1: minheight=0 maxheight=41.34 prefheight=39.37
HoleSize [All] p0: scope1count=1 scope1_0_kind=Board scope1_0_value=Board scope2count=1 scope2_0_kind=Board scope2_0_value=Board commentlength=0 absolutevalues=TRUE maxlimit=280 minlimit=5.9 maxpercent=80.000 minpercent=20.000
HoleSize [All] p1: absolutevalues=TRUE maxlimit=280 minlimit=5.9 maxpercent=80.000 minpercent=20.000
HoleToHoleClearance HoleToHoleClearance_1 [All] p0 off: scope1count=1 scope1_0_kind=Board scope1_0_value=Board scope2count=1 scope2_0_kind=Board scope2_0_value=Board commentlength=57 // Protel DXP Scope 1 Expression Was: WithinRoom('BGA1')
HoleToHoleClearance HoleToHoleClearance_1 [WithinRoom('BGA1')] p1: gap=4 allowstackedmicrovias=FALSE
LayerPairs [All] p0: scope1count=1 scope1_0_kind=Board scope1_0_value=Board scope2count=1 scope2_0_kind=Board scope2_0_value=Board commentlength=0 enforce=TRUE
MatchedLengths MatchedLengths_XDSET [All] p0 off: scope1count=1 scope1_0_kind=Board scope1_0_value=Board scope2count=1 scope2_0_kind=Board scope2_0_value=Board commentlength=62 tolerance=2.5 amplitude=200 gap=20 style=90-Degree // Protel DXP Scope 1 Expression Was: InxSignalClass('XDSET')
MatchedLengths MatchedLengths_CAN [All] p0 off: scope1count=1 scope1_0_kind=Board scope1_0_value=Board scope2count=1 scope2_0_kind=Board scope2_0_value=Board commentlength=60 tolerance=2.5 amplitude=200 gap=20 style=90-Degree // Protel DXP Scope 1 Expression Was: InxSignalClass('CAN')
MatchedLengths MatchedLengths_QSPI [All] p0 off: scope1count=1 scope1_0_kind=Board scope1_0_value=Board scope2count=1 scope2_0_kind=Board scope2_0_value=Board commentlength=61 tolerance=10 amplitude=200 gap=20 style=90-Degree // Protel DXP Scope 1 Expression Was: InxSignalClass('QSPI')
MatchedLengths MatchedLengths_RADAR_LVDS [All] p0 off: scope1count=1 scope1_0_kind=Board scope1_0_value=Board scope2count=1 scope2_0_kind=Board scope2_0_value=Board commentlength=67 tolerance=2.5 amplitude=200 gap=20 style=90-Degree // Protel DXP Scope 1 Expression Was: InxSignalClass('RADAR_LVDS')
MatchedLengths MatchedLengths_DCA_T [All] p0 off: scope1count=1 scope1_0_kind=Board scope1_0_value=Board scope2count=1 scope2_0_kind=Board scope2_0_value=Board commentlength=62 tolerance=5 amplitude=200 gap=20 style=90-Degree // Protel DXP Scope 1 Expression Was: InxSignalClass('DCA_T')
MatchedLengths MatchedLengths_XDS_T [All] p0 off: scope1count=1 scope1_0_kind=Board scope1_0_value=Board scope2count=1 scope2_0_kind=Board scope2_0_value=Board commentlength=62 tolerance=5 amplitude=200 gap=20 style=90-Degree // Protel DXP Scope 1 Expression Was: InxSignalClass('XDS_T')
MatchedLengths MatchedLengths_XDS_DCA_T [All] p0 off: scope1count=1 scope1_0_kind=Board scope1_0_value=Board scope2count=1 scope2_0_kind=Board scope2_0_value=Board commentlength=66 tolerance=5 amplitude=200 gap=20 style=90-Degree // Protel DXP Scope 1 Expression Was: InxSignalClass('XDS_DCA_T')
MatchedLengths MatchedLengths_RADAR_LVDS_DATA [All] p0: scope1count=1 scope1_0_kind=NetClass scope1_0_value=RADAR_LVDS_DATA scope2count=1 scope2_0_kind=Board scope2_0_value=Board commentlength=0 tolerance=5 amplitude=200 gap=20 style=90-Degree
MatchedLengths MatchedLengths_LVDS_D [All] p0: scope1count=1 scope1_0_kind=NetClass scope1_0_value=LVDS_D scope2count=1 scope2_0_kind=Board scope2_0_value=Board commentlength=0 tolerance=5 amplitude=200 gap=20 style=90-Degree
MatchedLengths MatchedLengths_LVDS_D [InNetClass('LVDS_D')] p1: tolerance=5 checknetsindiffpair=FALSE checkdiffpairvsdiffpair=TRUE checkxsignals=TRUE checkothers=TRUE
MatchedLengths MatchedLengths_XDS_DCA_T [InxSignalClass('XDS_DCA_T')] p2: tolerance=5 checknetsindiffpair=FALSE checkdiffpairvsdiffpair=TRUE checkxsignals=TRUE checkothers=TRUE
MatchedLengths MatchedLengths_XDSET [InxSignalClass('XDSET')] p3: tolerance=2.5 checknetsindiffpair=FALSE checkdiffpairvsdiffpair=TRUE checkxsignals=TRUE checkothers=TRUE
MatchedLengths MatchedLengths_DCA_T [InxSignalClass('DCA_T')] p4: tolerance=5 checknetsindiffpair=FALSE checkdiffpairvsdiffpair=TRUE checkxsignals=TRUE checkothers=TRUE
MatchedLengths MatchedLengths_XDS_T [InxSignalClass('XDS_T')] p5: tolerance=5 checknetsindiffpair=FALSE checkdiffpairvsdiffpair=TRUE checkxsignals=TRUE checkothers=TRUE
MatchedLengths MatchedLengths_QSPI [InxSignalClass('QSPI')] p6: tolerance=10 checknetsindiffpair=FALSE checkdiffpairvsdiffpair=TRUE checkxsignals=TRUE checkothers=TRUE
MatchedLengths MatchedLengths_CAN [InxSignalClass('CAN')] p7: tolerance=2.5 checknetsindiffpair=FALSE checkdiffpairvsdiffpair=TRUE checkxsignals=TRUE checkothers=TRUE
MatchedLengths MatchedLengths_RADAR_LVDS_DATA [InNetClass('RADAR_LVDS_DATA')] p8: tolerance=5 checknetsindiffpair=FALSE checkdiffpairvsdiffpair=TRUE checkxsignals=TRUE checkothers=TRUE
MatchedLengths MatchedLengths_RADAR_LVDS [InxSignalClass('RADAR_LVDS')] p9: tolerance=2.5 checknetsindiffpair=FALSE checkdiffpairvsdiffpair=TRUE checkxsignals=TRUE checkothers=TRUE
MinimumAnnularRing MinimumAnnularRing_ThermalPadVias [All] p0 off: scope1count=1 scope1_0_kind=Board scope1_0_value=Board scope2count=1 scope2_0_kind=Board scope2_0_value=Board commentlength=63 minimumring=3.9 // Protel DXP Scope 1 Expression Was: IsVia and InAnyComponent
MinimumAnnularRing [All] p0: scope1count=1 scope1_0_kind=Board scope1_0_value=Board scope2count=1 scope2_0_kind=Board scope2_0_value=Board commentlength=0 minimumring=3.9
MinimumAnnularRing MinimumAnnularRing_ThermalPadVias [IsVia and InAnyComponent] p1: minimumring=3.9
MinimumAnnularRing [All] p2: minimumring=3.9
MinimumSolderMaskSliver MinimumSolderMaskSliver_Logo [All] p0: scope1count=1 scope1_0_kind=ComponentClass scope1_0_value=Logo scope2count=1 scope2_0_kind=ComponentClass scope2_0_value=Logo commentlength=0
MinimumSolderMaskSliver [All] p0: scope1count=1 scope1_0_kind=Board scope1_0_value=Board scope2count=1 scope2_0_kind=Board scope2_0_value=Board commentlength=0
MinimumSolderMaskSliver MinimumSolderMaskSliver_Logo [InComponentClass('Logo') vs InComponentClass('Logo')] p1: minsoldermaskwidth=0.7
MinimumSolderMaskSliver [All] p2: minsoldermaskwidth=3.5
NetAntennae [All] p0: scope1count=1 scope1_0_kind=Board scope1_0_value=Board scope2count=1 scope2_0_kind=Board scope2_0_value=Board commentlength=0
PasteMaskExpansion [All] p0: scope1count=1 scope1_0_kind=Board scope1_0_value=Board scope2count=1 scope2_0_kind=Board scope2_0_value=Board commentlength=0 expansion=0
PlaneClearance [All] p0: scope1count=1 scope1_0_kind=Board scope1_0_value=Board scope2count=1 scope2_0_kind=Board scope2_0_value=Board commentlength=0 clearance=20
PlaneConnect [All] p0: scope1count=1 scope1_0_kind=Board scope1_0_value=Board scope2count=1 scope2_0_kind=Board scope2_0_value=Board commentlength=0 planeconnectstyle=Relief reliefexpansion=10 reliefentries=4 reliefconductorwidth=10 reliefairgap=10
PlaneConnect [All] p1: planeconnectstyle=Relief reliefexpansion=10 reliefentries=4 reliefconductorwidth=10 reliefairgap=10
PolygonConnect [All] p0: scope1count=1 scope1_0_kind=Board scope1_0_value=Board scope2count=1 scope2_0_kind=Board scope2_0_value=Board commentlength=0 connectstyle=Direct reliefconductorwidth=10 reliefentries=4 polygonreliefangle="90 Angle"
PolygonConnect [All] p1: connectstyle=Direct reliefconductorwidth=10 reliefentries=4 polygonreliefangle="90 Angle" airgapwidth=10
RoomDefinition BGA1 [All] p0: scope1count=1 scope1_0_kind=ComponentClass scope1_0_value="Components Class 2" scope2count=1 scope2_0_kind=Board scope2_0_value=Board commentlength=0 region_x1=26189220 region_y1=36725756 region_x2=30877160 region_y2=40862795 confinementstyle=ConfineIn
RoomDefinition BGA1 [InComponentClass('Components Class 2')] p1: confinementstyle=ConfineIn formatcopy=TRUE lockcomponents=FALSE outline 1045.03,2611.54 1513.83,2611.54 1513.83,2197.84 1045.03,2197.84
RoutingCorners [All] p0: scope1count=1 scope1_0_kind=Board scope1_0_value=Board scope2count=1 scope2_0_kind=Board scope2_0_value=Board commentlength=0 cornerstyle=45-Degree minsetback=100 maxsetback=100
RoutingLayers [All] p0: scope1count=1 scope1_0_kind=Board scope1_0_value=Board scope2count=1 scope2_0_kind=Board scope2_0_value=Board commentlength=0 top layer=Automatic mid layer 1=Automatic mid layer 2=Automatic mid layer 3=Automatic mid layer 4=Automatic mid layer 5=Automatic mid layer 6=Automatic bottom layer=Automatic
RoutingPriority [All] p0: scope1count=1 scope1_0_kind=Board scope1_0_value=Board scope2count=1 scope2_0_kind=Board scope2_0_value=Board commentlength=0
RoutingTopology [All] p0: scope1count=1 scope1_0_kind=Board scope1_0_value=Board scope2count=1 scope2_0_kind=Board scope2_0_value=Board commentlength=0 topology=Shortest
RoutingVias ThermalPadVias [All] p0 off: scope1count=1 scope1_0_kind=Board scope1_0_value=Board scope2count=1 scope2_0_kind=Board scope2_0_value=Board commentlength=63 holewidth=7.87 width=19.68 viastyle="Through Hole" minholewidth=5 minwidth=13 maxholewidth=12.99 maxwidth=23.62 // Protel DXP Scope 1 Expression Was: IsVia and InAnyComponent
RoutingVias [All] p0: scope1count=1 scope1_0_kind=Board scope1_0_value=Board scope2count=1 scope2_0_kind=Board scope2_0_value=Board commentlength=0 holewidth=12.2 width=22.4 viastyle="Through Hole" minholewidth=5.9 minwidth=14 maxholewidth=20 maxwidth=40
RoutingVias ThermalPadVias [IsVia and InAnyComponent] p1: holewidth=7.87 width=19.68 viastyle="Through Hole" minholewidth=5 minwidth=13 maxholewidth=12.99 maxwidth=23.62
RoutingVias [All] p2: holewidth=12.2 width=22.4 viastyle="Through Hole" minholewidth=5.9 minwidth=14 maxholewidth=20 maxwidth=40
SMDToCorner [All] p0: scope1count=1 scope1_0_kind=Board scope1_0_value=Board scope2count=1 scope2_0_kind=Board scope2_0_value=Board commentlength=0 distance=25000
SMDToCorner [All] p1: distance=25000
ShortCircuit [All] p0: scope1count=1 scope1_0_kind=Board scope1_0_value=Board scope2count=1 scope2_0_kind=Board scope2_0_value=Board commentlength=0 allowed=FALSE
SilkToBoardRegionClearance [All] p0 off: scope1count=1 scope1_0_kind=Board scope1_0_value=Board scope2count=1 scope2_0_kind=Board scope2_0_value=Board commentlength=130 // Protel DXP Scope 1 Expression Was: Not ((IsComment or IsDesignator) And (Hide <> 'False')) and not InRegion(1000,500,4000,800)
SilkToBoardRegionClearance [Not ((IsComment or IsDesignator) And (Hide <> 'False')) and not InRegion(1000,500,4000,800)] p1:
SilkToSilkClearance [All] p0: scope1count=1 scope1_0_kind=Board scope1_0_value=Board scope2count=1 scope2_0_kind=Board scope2_0_value=Board commentlength=0
SilkToSilkClearance [All] p1: silktosilkclearance=3
SilkToSolderMaskClearance SilkToSolderMaskClearance_OutLine [All] p0 off: scope1count=1 scope1_0_kind=Board scope1_0_value=Board scope2count=1 scope2_0_kind=Board scope2_0_value=Board commentlength=65 // Protel DXP Scope 1 Expression Was: istrack and InAnyComponent
SilkToSolderMaskClearance SilkscreenOverComponentPads [All] p0 off: scope1count=1 scope1_0_kind=Board scope1_0_value=Board scope2count=1 scope2_0_kind=Board scope2_0_value=Board commentlength=44 // Protel DXP Scope 1 Expression Was: IsPad
SilkToSolderMaskClearance SilkToSolderMaskClearance_OutLine [istrack and InAnyComponent] p1: minsilkscreentomaskgap=0 clearancetoexposedcopper=FALSE
SilkToSolderMaskClearance SilkscreenOverComponentPads [IsPad] p2: minsilkscreentomaskgap=3 clearancetoexposedcopper=FALSE
SolderMaskExpansion [All] p0: scope1count=1 scope1_0_kind=Board scope1_0_value=Board scope2count=1 scope2_0_kind=Board scope2_0_value=Board commentlength=0 expansion=0
SolderMaskExpansion [All] p1: expansion=0 istentingtop=FALSE
UnRoutedNet [All] p0: scope1count=1 scope1_0_kind=Board scope1_0_value=Board scope2count=1 scope2_0_kind=Board scope2_0_value=Board commentlength=0
UnRoutedNet [All] p1: checkbadconnections=TRUE
UnpouredPolygon [All] p0: scope1count=1 scope1_0_kind=Board scope1_0_value=Board scope2count=1 scope2_0_kind=Board scope2_0_value=Board commentlength=0
Width [All] p0: scope1count=1 scope1_0_kind=Board scope1_0_value=Board scope2count=1 scope2_0_kind=Board scope2_0_value=Board commentlength=0 maxlimit=100 minlimit=4 preferedwidth=10
Width [All] p1: maxlimit=100 minlimit=4 preferedwidth=10 toplayer_prefwidth=6 midlayer1_minwidth=6 midlayer2_minwidth=6 midlayer3_minwidth=6 midlayer4_minwidth=6 midlayer5_minwidth=6 midlayer6_minwidth=6 minimp=50.000000 maximp=50.000000 favimp=50.000000
12 further rules are at their usual default settings.

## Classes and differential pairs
net class RADAR_LVDS_DATA: RADAR_LVDS_CLK RADAR_LVDS_DATA0 RADAR_LVDS_DATA1 RADAR_LVDS_DATA2 RADAR_LVDS_DATA3 RADAR_LVDS_FRCLK
net class LVDS_D: LVDS_CLK_RTC_CLKIN_TP LVDS_D0_LIN_PHY_RX LVDS_D1_XDS_UARTA_RX_CAN_RX LVDS_D2_XDS_UARTA_TX_CAN_TX LVDS_D3_nERROR_LED_WD_TP LVDS_FRCLK_HOST_CLK_TP
net class POWER: 3V3_LDO_EN 5V_IN 5V_IN_USB 5V_REG CB_REG_1V2 CB_REG_1V8 CB_REG_RF_1V2 CONN_5V PMIC_CLKOUT PMIC_CLKOUT_LIN_PHY_TX_SOP1 REG_1V2 REG_1V8 REG_3V3 REG_OUT_1V2 REG_OUT_1V8 REG_OUT_3V3 REG_PG REG_RF_1V2 SW_PR1
component class PROC117B_XDS110_Interface_1B: C94 C95 C97 C98 C99 C102 R24 R26 R122 R124 R125 R126 R169 R170 R181 R188 R190 R191 R194 R195 R196 R197 R199 R202 R231 R233 R234 S5 U21 U22 Y2
component class PROC117B_XDS110_Interface_1A: C42 C43 C105 C106 C108 C113 C114 C115 C116 C117 C118 C124 C125 C126 C127 R9 R10 R11 R12 R236 R239 R241 U13
component class PROC117B_DC_Regulators: C54 C56 C60 C61 C62 C66 C67 C68 C69 C70 C71 C72 C73 C74 C79 C87 C100 C107 C119 C120 C121 C122 C128 C129 C130 C131 L1 L4 L5 L6 L11 L13 L14 L15 Q3 R43 R119 R121 R173 R175 R176 R177 R178 R180 R198 R201 R232 R238 R244 TP9 TP11 U18 U19 U20
net class Regions: 5V_IN 5V_IN_USB GND NetD1_2 NetD2_2 XTALP
component class Logo: Logo1
component class FiducialMark: FID1 FID2 FID3 FID4 FID5 FID6
component class Label: LBL1
component class PROC117B_Decoupling_caps: C1 C4 C5 C6 C7 C8 C9 C10 C11 C12 C13 C14 C15 C16 C17 C18 C19 C20 C21 C22 C23 C24 C25 C26 C27 C28 C29 C30 C44 C45 C64 C80 C81 C82 C83 C101 C103 C104 C109 C110 C111 C112 R92 R182 R183
component class PROC117B_EVM_Hardware: "CAUTION HOT SURFACE1" FID1 FID2 FID3 FID4 FID5 FID6 LBL1 Logo1 Logo2 LOGO3 Logo4 ZZ1 ZZ2 ZZ3 ZZ4 ZZ5
component class PROC117B_LP_BP_Connector: C76 C77 J1 J2 J8 J9 R35 R36 R77 R83 R84 R85 R87 R95 R96 R97 R98 R99 R100 R118 R132 R133 R140 R143 R144 R145 R146 R147 R149 R153 R154 R155 R163 R164
component class PROC117B_xWRL6432_Chip: C3 C31 C32 C33 C78 R4 R20 R23 R67 R73 R74 R75 R81 R82 R86 R89 R93 R131 R152 TP5 TP6 TP7 TP10 U1 Y1
component class PROC117B_CAN_LIN_PHY_Interface: C37 C38 C39 C123 C132 D8 J3 J4 R3 R17 R18 R19 R21 R22 R31 R32 R68 R69 R71 R78 R79 R80 R88 U5 U23
component class PROC117B_QSPI_Flash_LVDS_Driver: C34 C35 C75 C88 C89 C90 C91 R44 R45 R46 R47 R48 R49 R50 R51 R90 R91 R129 R130 TP2 TP3 TP4 U2 U10 U14 U15
component class PROC117B_Temp_Current_sensors_EPROM: C36 C57 C58 C59 C65 C133 R2 R14 R25 R29 R54 R55 R56 R57 R94 R101 R103 R104 R105 R106 R107 R108 R109 R110 R111 R112 R113 R114 R115 R116 R117 R134 R135 R136 R137 R139 R142 R148 R150 R151 R157 R158 R159 R160 R161 R162 R192 R193 R200 U3 U6 U7 U8 U11 U25
net class "TX and RX": RX1 RX2 RX3 TX1 TX2
component class AssemblyNote: ZZ1 ZZ2 ZZ3 ZZ4 ZZ5
component class PROC117B_USB_PWR_DC_Jack_Switch: C46 C47 C48 C49 C50 C51 C55 C63 C84 C85 C86 C134 C135 C136 C137 D1 D2 D3 D4 D6 F1 FB1 FB2 FL1 FL2 J5 J7 L9 LD1 Q2 R1 R72 R76 R102 R120 R172 R174 R179 TP8 TP12 U9 U16
component class PROC117B_DCA1000_Connector_Reset: C52 C53 C92 C93 C96 D5 D7 D9 J6 LD2 LD4 Q1 Q4 R28 R30 R34 R37 R38 R39 R40 R41 R42 R52 R53 R58 R59 R60 R61 R62 R63 R64 R65 R66 R123 R138 R141 R165 R171 R213 R214 R215 R219 R220 R221 R222 R223 R224 R225 R226 R227 R228 R229 R230 S2 S3 SW1 SW2 U17
component class Header: Case FL3 FL4 J1 J2 LD3
component class PROC117B_Analog_Mux_SOP_Ctrl: C2 C40 C41 R5 R6 R7 R8 R13 R15 R16 R27 R33 R70 R127 R128 R156 R203 R204 R205 R206 R207 R208 S1 S4 TP1 U4 U12 U24

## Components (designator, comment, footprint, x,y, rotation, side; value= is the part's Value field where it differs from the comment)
C1 "CGA5L1X7R0J226M160AC" 1206_180 1890.39,2264.5 r180 bottom
C2 "C0402C104K8RACTU" 0402 1843.46,1002.34 r270 bottom
C3 "GRT155R70J105KE01D" FP-GRT155R70J105KE01D_0402-MFG 905.75,2440.84 r0 top
C4 "GCM155R71C224KE02D" 0402L 1123.42,2471.28 r0 bottom
C5 "GCM155R71C224KE02D" 0402L 1215,2449.62 r90 bottom
C6 "CGA2B3X7R1H473K050BB" 0402L 1125.93,2413.9 r270 bottom
C7 "GCM155R71C224KE02D" 0402L 1139.43,2236.79 r90 top
C8 "GCM155R71C224KE02D" 0402L 1021.84,2358.67 r0 bottom
C9 "GRT155C71A225KE13D" FP-GRT155C71A225KE13D_0402-MFG 982.61,2555.18 r270 top
C10 "GCM155R71C224KE02D" 0402L 1353.39,2349.97 r90 bottom
C11 "GCM155R71C224KE02D" 0402L 1084.79,2410.91 r90 bottom
C12 "GCM155R71C224KE02D" 0402L 1046.09,2413.28 r90 bottom
C13 "GCM188D70J106ME36D" FP-GCM188D70J106ME36D_0603-MFG 1454.44,2330.49 r270 bottom
C14 "GCM155R71C224KE02D" 0402L 1311.15,2405.01 r180 bottom
C15 "GCM188D70J106ME36D" FP-GCM188D70J106ME36D_0603-MFG 1403.65,2330.49 r270 bottom
C16 "GCM155R71C224KE02D" 0402L 1220.59,2253.5 r270 bottom
C17 "GRT155C71A225KE13D" FP-GRT155C71A225KE13D_0402-MFG 1031.69,2295.29 r90 top
C18 "GRT155R70J105KE01D" FP-GRT155R70J105KE01D_0402-MFG 1267.12,2458.22 r90 bottom
C19 "GCM155R71C224KE02D" 0402L 1023.28,2556 r270 top
C20 "GRT155C71A225KE13D" FP-GRT155C71A225KE13D_0402-MFG 970.45,2452.15 r90 bottom
C21 "GCM155R71C224KE02D" 0402L 1066.08,2293.29 r90 top
C22 "GRT155R70J105KE01D" FP-GRT155R70J105KE01D_0402-MFG 1174.63,2468.14 r270 bottom
C23 "GCM188D70J106ME36D" FP-GCM188D70J106ME36D_0603-MFG 938.14,2563.04 r90 top
C24 "GCJ21BR71C475KA01L" FP-GCJ21BR71C475KA01L_0805-MFG 884.66,2485.72 r0 bottom
C25 "GCM155R71C224KE02D" 0402L 1084.65,2312.53 r90 bottom
C26 "GCM155R71C224KE02D" 0402L 1035.23,2386.33 r90 top
C27 "GCJ21BR71C475KA01L" FP-GCJ21BR71C475KA01L_0805-MFG 1001.46,2284.43 r90 bottom
C28 "GCM155R71C224KE02D" 0402L 1294.28,2312.73 r0 bottom
C29 "GCM155R71C224KE02D" 0402L 1203.42,2380.12 r180 bottom
C30 "GCM155R71E103KA37D" 0402L 1051.43,2304.11 r270 bottom
C31 "GRM033C71A104KE14D" 0201 1622.85,2348 r180 top
C32 "GJM1555C1H4R7BB01D" 0402L 1438.16,2658.32 r180 bottom
C33 "GJM1555C1H4R7BB01D" 0402L 1494.18,2607.42 r270 bottom
C34 "GCM155R71H104KE02D" 0402 1200.21,1775.36 r180 bottom
C35 "GCM188R71C105KA64D" 0603 1190.28,1714.68 r0 bottom
C36 "GCM155R71H104KE02D" 0402 1391.8,573.31 r180 bottom
C37 "C0402C104K8RACTU" 0402L 272.47,1882.94 r0 top
C38 "C0402C104K8RACTU" 0402L 549.71,1763.38 r90 top
C39 "GCM155R71H472KA37D" 0402L 301.17,1959.5 r90 top
C40 "C0402C104K8RACTU" 0402 1096.63,1125.93 r90 top
C41 "C0402C104K8RACTU" 0402 1184.63,240.2 r90 bottom
C42 "C1005X7S1A225K050BC" 0402_065L 1756.37,857.71 r180 bottom
C43 "C0402C104K8RACTU" 0402L 1756.34,890.66 r180 bottom
C44 "GCM188D70J106ME36D" FP-GCM188D70J106ME36D_0603-MFG 905.16,2539.19 r180 bottom
C45 "GCM155R71E103KA37D" 0402L 1203.42,2313.75 r0 bottom
C46 "CL05A106MP5NUNC" 0402_070 1778.87,969 r90 top
C47 "CL05A106MP5NUNC" 0402_070 1743.78,968.71 r270 top
C48 "T491B476K010AT" 3528-21 1394.67,573.28 r270 top
C49 "GRM033R6YA104KE14D" "FP-GRM033R6YA104KE14D_0201 (0603 Metric)-IPC_C" 1459.91,1084.69 r90 top
C50 "GRM033R6YA104KE14D" "FP-GRM033R6YA104KE14D_0201 (0603 Metric)-IPC_C" 1597.32,1034.09 r270 top
C51 "GRT155C81A105KE01D" 0402L 1505.69,1194.27 r180 top
C52 "GRM033R6YA104KE14D" "FP-GRM033R6YA104KE14D_0201 (0603 Metric)-IPC_C" 1263.76,226.49 r0 bottom
C53 "GCM155R71H104KE02D" 0402 1107.4,78.56 r270 top
C54 "GRM31CR70J226ME19K" FP-GRM31CR70J226ME19K_1206-MFG 1760.05,1900.02 r180 top
C55 "GRM31CR61A476KE15L" 1206_180 1843.68,954.56 r270 top
C56 "GRM188Z71A106MA73D" 0603_HV 1670.97,1377.28 r90 top
C57 "GCM155R71H104KE02D" 0402 1642.68,2033.99 r270 bottom
C58 "GCM155R71H104KE02D" 0402 1647.13,1645.63 r180 bottom
C59 "GCM155R71H104KE02D" 0402 453.1,2085.59 r180 top
C60 "GRM188R71C474KA88D" 0603S 1725.75,1385.2 r90 top
C61 "GRM31CR70J226ME19K" FP-GRM31CR70J226ME19K_1206-MFG 786.45,2351.57 r180 bottom
C62 "GRM188Z71A106MA73D" 0603_HV 459.8,2359.96 r90 bottom
C63 "T491B476K010AT" 3528-21 1262.13,573.97 r270 top
C64 "CGA5L1X7R0J226M160AC" 1206_180 644.27,2102.05 r90 top
C65 "GCM155R71H104KE02D" 0402 2284.36,1820.25 r90 top
C66 "GRM188R71C474KA88D" 0603S 409.72,2364.32 r90 bottom
C67 "GRM1555C1H471JA01D" 0402L 368.44,2367.1 r90 bottom
C68 "GRM31CR60J476ME19L" 1206_180 2003.7,2189.12 r180 top
C69 "GRM1555C1H471JA01D" 0402L 1766.52,1374.1 r90 top
C70 "GRM188Z71A106MA73D" 0603 1720.73,1482.09 r180 top
C71 "GRM188Z71A106MA73D" 0603 1720.73,1544.24 r180 top
C72 "GRM188Z71A106MA73D" 0603_HV 1621.82,2189.12 r0 top
C73 "GRM188R71C474KA88D" 0603S 1619.39,2137.76 r0 top
C74 "GRM1555C1H471JA01D" 0402L 1619.53,2097.31 r0 top
C75 "GCM155R71H104KE02D" 0402 1007.17,1335.29 r180 top
C76 "GCM155C71A474KE36D" 0402L 232.85,2194.19 r180 bottom
C77 "GCM155C71A474KE36D" 0402L 626.25,2150.58 r270 bottom
C78 "GRT155R70J105KE01D" FP-GRT155R70J105KE01D_0402-MFG 2202.3,2274.58 r90 bottom
C79 "GRM31CR70J226ME19K" FP-GRM31CR70J226ME19K_1206-MFG 344.97,2726.88 r0 bottom
C80 "CGA4J1X7T0J226M125AC" FP-CGA4J1X7T0J226M125AC_0805-MFG 727.27,2140.6 r90 top
C81 "CGA4J1X7T0J226M125AC" FP-CGA4J1X7T0J226M125AC_0805-MFG 801.35,2141.06 r90 top
C82 "CGA4J1X7T0J226M125AC" FP-CGA4J1X7T0J226M125AC_0805-MFG 1678.18,2313.55 r90 bottom
C83 "CGA4J1X7T0J226M125AC" FP-CGA4J1X7T0J226M125AC_0805-MFG 1607.68,2313.75 r90 bottom
C84 "GCM155C71A474KE36D" 0402L 1708.4,970.69 r270 top
C85 "GCM155R71C224KE02D" 0402L 1673,970.13 r90 top
C86 "GRT188R61A106KE13D" 0603S 2225.95,857.71 r90 top
C87 "GRM31CR70J226ME19K" FP-GRM31CR70J226ME19K_1206-MFG 1697.39,1619.07 r0 top
C88 "GCM155R71E103KA37D" 0402L 1049.58,1377.59 r0 top
C89 "GCM155R71H104KE02D" 0402 1533.26,1547.38 r0 top
C90 "GCM155R71E103KA37D" 0402L 1531.35,1502.8 r0 top
C91 "GCM155R71H104KE02D" 0402 1062.8,1913.02 r0 bottom
C92 "GCM155C71A474KE36D" 0402L 157.07,1264.5 r180 top
C93 "GRT155C81A105KE01D" 0402L 154.86,1299.23 r180 top
C94 "C0402C104K8RACTU" 0402L 1391.73,1494 r0 bottom
C95 "C0402C104K8RACTU" 0402L 809.26,1531.47 r0 bottom
C96 "GRT188R61A106KE13D" 0603S 148.1,1337.28 r0 top
C97 "CC0402DRNPO9BN8R0" 0402L 1261.04,1578.25 r270 bottom
C98 "CC0402DRNPO9BN8R0" 0402L 1050.36,1609.21 r0 bottom
C99 "C0402C104K8RACTU" 0402L 1128.55,753.54 r0 bottom
C100 "CGA2B2C0G1H100D050BA" 0402 231.43,2502.3 r270 bottom
C101 "GCM155R71C224KE02D" 0402L 1028.73,2508.5 r270 bottom
C102 "GCM155R71E103KA37D" 0402L 1128.65,789.42 r0 bottom
C103 "CGA5L1X7R0J226M160AC" 1206_180 597.52,2752.94 r90 bottom
C104 "CGA4J1X7T0J226M125AC" FP-CGA4J1X7T0J226M125AC_0805-MFG 754.41,2756.34 r270 bottom
C105 "C1005X7S1A225K050BC" 0402_065L 1825.81,692.81 r0 bottom
C106 "C0402C104K8RACTU" 0402L 1404.89,983.75 r90 bottom
C107 "GRM31CR70J226ME19K" FP-GRM31CR70J226ME19K_1206-MFG 1697.66,1703.09 r0 top
C108 "GRT155C81A105KE01D" 0402L 1399.6,1314.83 r270 bottom
C109 "GCM21BR71A106KE22L" 0805_HV 1529.64,2298.22 r270 bottom
C110 "GCM21BR71A106KE22L" 0805_HV 889.69,2137.84 r270 top
C111 "CGA4J1X7T0J226M125AC" FP-CGA4J1X7T0J226M125AC_0805-MFG 826.32,2757.22 r270 bottom
C112 "GCM21BR71A106KE22L" 0805_HV 876.42,2609.89 r180 bottom
C113 "C0402C104K8RACTU" 0402L 888.65,757.29 r90 bottom
C114 "GRT155C81A105KE01D" 0402L 852.08,756.34 r270 bottom
C115 "GCM155R71E103KA37D" 0402L 1258.15,1138.62 r180 top
C116 "C0402C104K8RACTU" 0402L 1033.55,784.51 r0 bottom
C117 "04025A150FAT2A" 0402L 1858.8,756.14 r270 bottom
C118 "GCM155R71E103KA37D" 0402L 1316.92,773.94 r90 bottom
C119 "GRM188Z71A106MA73D" 0603 391.96,2487.43 r270 bottom
C120 "GRM188Z71A106MA73D" 0603 456.39,2487.63 r270 bottom
C121 "GRM31CR70J226ME19K" FP-GRM31CR70J226ME19K_1206-MFG 531.02,2472.43 r90 bottom
C122 "GRM31CR70J226ME19K" FP-GRM31CR70J226ME19K_1206-MFG 610.06,2472.47 r90 bottom
C123 "GCM155R71H104KE02D" 0402 315.3,2651.2 r180 top
C124 "C1005X7S1A225K050BC" 0402_065L 1170.32,1360.86 r90 top
C125 "C0402C104K8RACTU" 0402L 1138.59,1360.59 r90 top
C126 "C0402C104K8RACTU" 0402L 1438.99,1133.17 r270 bottom
C127 "GRT155C81A105KE01D" 0402L 1399.6,1132.82 r90 bottom
C128 "GRM188Z71A106MA73D" 0603 1749.89,2114.25 r180 top
C129 "GRM188Z71A106MA73D" 0603 1751.32,2177.04 r180 top
C130 "GRM31CR70J226ME19K" FP-GRM31CR70J226ME19K_1206-MFG 1768.73,2246.78 r0 top
C131 "GRM31CR70J226ME19K" FP-GRM31CR70J226ME19K_1206-MFG 1768.74,2322.39 r0 top
C132 "885012005063" 0402 431.09,2779.11 r0 top
C133 "GCM155R71H104KE02D" 0402 541.6,2934.41 r90 bottom
C134 "GCM155R71H104KE02D" 0402 1505.71,1153.46 r180 top
C135 "GRM188Z71A106MA73D" 0603 1501.69,1245.32 r180 top
C136 "GRT155C81A105KE01D" 0402L 1424.54,1084.1 r90 top
C137 "GRT155C81A105KE01D" 0402L 1630.46,1038.75 r270 top
"CAUTION HOT SURFACE1" "CAUTION HOT SURFACE" IEC_HotSurface_Small 1677.51,1263.39 r180 bottom
D1 "PMEG3020EP,115" SOD-128 2033.83,973.95 r0 top
D2 "PMEG3020EP,115" SOD-128 1304.96,971.79 r180 top
D3 "TLMY1000-GS08" TLMx1000_Yellow 1369.84,105.75 r180 top
D4 "SZP6SMB6.8AT3G" SMB 1546.36,573.19 r270 top
D5 "APHHS1005CGCK" APHHS1005_Green 1766.25,125.18 r0 top
D6 "APHHS1005CGCK" APHHS1005_Green 1708.19,1202.37 r180 top
D7 "APHHS1005CGCK" APHHS1005_Green 1589.36,129.53 r0 top
D8 "PMEG3020EP,115" SOD-128 153.73,2504.42 r90 top
D9 "APHHS1005SURCK" APHHS1005_Red 1435.28,1820.13 r270 top
F1 "32V, 5A" 1206 1739.66,646.54 r0 top
FB1 "BLM21PG300SH1D" 0805_HV 1385.79,775.51 r90 top
FB2 "BLM21PG300SH1D" 0805_HV 1297.44,775.51 r90 top
FID1 "Fiducial" Fiducial10-20 140.72,2925.06 r0 top
FID2 "Fiducial" Fiducial10-20 392.01,109.7 r90 bottom
FID3 "Fiducial" Fiducial10-20 140.72,2925.06 r90 bottom
FID4 "Fiducial" Fiducial10-20 392.01,109.7 r0 top
FID5 "Fiducial" Fiducial10-20 2111.3,109.7 r90 bottom
FID6 "Fiducial" Fiducial10-20 2111.3,109.7 r0 top
J1 "61300311021" Wurth_61300311021 166.94,1669.18 r90 bottom
J2 "PBC07SAAN" Sullins_xxC07SAAN 2420.41,1520.3 r270 top
J3 "M50-3930342" FP-M50-3930342_HDR3-MFG 27.72,2064.66 r90 bottom
J4 "M50-3930442" FP-M50-3930442_HDR4-Recommended_Land_Pattern 27.72,2783.93 r90 bottom
J5 "105017-0001" CONN_105017-0001 2371.29,964.23 r90 top locked
J6 "QSH-030-01-L-D-A" Samtec_QSH-030-01-X-D-A 355.62,946.88 r0 top locked
J7 "PJ-002AH" CUI_PJ-002AH 2058.68,468.89 r0 top locked
J8 "SSM-110-S-DV" Samtec_SSM-110-x-DV 440.9,1743.67 r270 bottom locked
J9 "SSM-110-S-DV" Samtec_SSM-110-x-DV 2140.83,1743.63 r270 bottom locked
L1 "LQM2MPZR10MJHL" "FP-LQM2MPZR10MJHL_0806 (2016)-MFG" 433.65,2621 r90 bottom
L4 "LQM2MPZR10MJHL" "FP-LQM2MPZR10MJHL_0806 (2016)-MFG" 1724.58,1799.9 r180 top
L5 "LQM2MPZR10MJHL" "FP-LQM2MPZR10MJHL_0806 (2016)-MFG" 726.26,2467.43 r270 bottom
L6 "LQM2MPZR10MJHL" "FP-LQM2MPZR10MJHL_0806 (2016)-MFG" 1906.87,2304.76 r0 top
L9 "BLM15PD300SZ1D" 0402L 2148.55,888.72 r180 top
L11 "BLM15PD300SZ1D" 0402L 1634.64,1856.9 r180 top
L13 "DFE201210U-R47M=P2" "FP-DFE201210U-R47M=P2_0805 (2012)-MFG" 1831.01,1502.36 r90 top
L14 "DFE201210U-R47M=P2" "FP-DFE201210U-R47M=P2_0805 (2012)-MFG" 313.5,2501.7 r90 bottom
L15 "DFE201210U-R47M=P2" "FP-DFE201210U-R47M=P2_0805 (2012)-MFG" 1758.62,2035.59 r0 top
LBL1 "THT-14-423-10" Label_650x200 128.4,784.83 r270 bottom
Logo1 "Texas Instruments" TI_Stacked_Overlay_Small 755.35,1609.21 r0 top
Logo2 "CE Mark" CE_Mark_5mm 1736.75,317.37 r180 bottom
LOGO3 "FCC disclaimer" FCC_disclaimer 1069.2,3013.89 r180 bottom (schematic designator Logo3)
Logo4 "WEEE logo" WEEE_Minimum 126.49,399.87 r0 top
Q1 "BSS123W-7-F" SOT-323 1783.06,206.2 r270 top
Q2 "BSS123W-7-F" SOT-323 1340.76,189.01 r270 top
Q3 "BSS123W-7-F" SOT-323 1505.02,1451.5 r180 bottom
Q4 "BSS123W-7-F" SOT-323 1606.8,207.8 r270 top
R1 "MCT06030Z0000ZP500" 0603 1994.01,1075.79 r180 top
R2 "CRCW040210K0FKED" 0402L 1807.48,1844.36 r0 bottom
R3 "ERJ-2GE0R00X" 0402 656.83,1931.06 r180 top
R4 "CRCW040210K0FKED" 0402L 1288.24,2050.51 r270 top
R5 "CRCW040210K0FKED" 0402L 635,3125.49 r180 bottom
R6 "CRCW04024K70JNED" 0402 1064.46,1019.14 r0 top
R7 "CRCW040210K0FKED" 0402L 1182.53,118.04 r0 bottom
R8 "CRCW040210K0FKED" 0402L 868.82,354.85 r90 bottom
R9 "MCT06030Z0000ZP500" 0603 1640.53,954.56 r0 bottom
R10 "CRCW040249K9FKED" 0402L 1826.83,756.3 r270 bottom
R11 "CRCW0402100KFKED" 0402L 1604.24,753.71 r180 bottom
R12 "CRCW040230K0FKED" 0402L 1695.97,691.25 r180 bottom
R13 "CRCW0402750RFKED" 0402L 782.9,459.76 r0 top
R14 "CRCW040210K0FKED" 0402L 1860.96,1904.72 r0 bottom
R15 "ERJ-2GE0R00X" 0402L 1091.59,420.71 r270 top
R16 "CRCW0402750RFKED" 0402L 947.67,420.82 r90 top
R17 "CRCW040210K0FKED" 0402L 589.92,2674.25 r0 top
R18 "ERJ-2GE0R00X" 0402 541.58,2605.17 r180 top
R19 "ERJ-2GE0R00X" 0402 546.98,2775.75 r180 top
R20 "CRCW040210K0FKED" 0402L 2092.59,2321.96 r90 top
R21 "CRCW04021K00FKED" 0402 442.07,2572.96 r270 top
R22 "CRCW040210K0FKED" 0402L 609.31,2585.47 r270 top
R23 "CRCW040210K0FKED" 0402L 1999.04,1161.7 r180 bottom
R24 "ERJ-2GE0R00X" 0402 603.36,814.59 r90 bottom
R25 "CRCW02010000Z0ED" 0201 1648.77,1918.09 r90 bottom
R26 "ERJ-2GE0R00X" 0402 759.17,743.81 r180 bottom
R27 "CRCW040210K0FKED" 0402L 1779.34,1019.16 r0 bottom
R28 "RC0201JR-07510RL" 0201L 1536.57,117.51 r90 top
R29 "CRCW02010000Z0ED" 0201 1704.5,1841.58 r180 bottom
R30 "MCT06030Z0000ZP500" 0603 212.59,1406.54 r180 top
R31 "MCT06030Z0000ZP500" 0603 307.86,2714.2 r0 top
R32 "MCT06030Z0000ZP500" 0603 307.86,2783.93 r0 top
R33 "CRCW04024K70JNED" 0402 1912.13,1012.13 r90 bottom
R34 "CRCW02010000Z0ED" 0201_Silk 528.61,1318.63 r90 top
R35 "CRCW02010000Z0ED" 0201_Silk 248.36,2041.94 r270 bottom
R36 "CRCW02010000Z0ED" 0201_Silk 248.36,1830.76 r90 bottom
R37 "CRCW02010000Z0ED" 0201_Silk 126.49,1223.18 r180 top
R38 "CRCW02010000Z0ED" 0201_Silk 573.4,1318.63 r90 top
R39 "CRCW02010000Z0ED" 0201_Silk 100.51,1191.19 r0 top
R40 "CRCW02010000Z0ED" 0201_Silk 597.77,1201.56 r90 top
R41 "CRCW02010000Z0ED" 0201_Silk 100.51,1146.48 r0 top
R42 "CRCW02010000Z0ED" 0201_Silk 603.93,1149.93 r0 top
R43 "CRCW040218K0FKED" 0402L 1919.35,1353.77 r270 top
R44 "CRCW040210K0FKED" 0402L 1388.36,2090.43 r180 bottom
R45 "CRCW020133R2FNED" 0201_Silk 1441.84,1708.03 r270 bottom
R46 "CRCW020133R2FNED" 0201_Silk 1340.12,2042.1 r270 bottom
R47 "CRCW020133R2FNED" 0201_Silk 1390.12,2042.1 r270 bottom
R48 "CRCW020133R2FNED" 0201_Silk 1390.23,1709.81 r270 bottom
R49 "CRCW040210K0FKED" 0402L 1290.46,1706.34 r90 bottom
R50 "AC0402FR-0747K5L" FP-AC0402FR-0747K5L_0402-MFG 1270.43,2024.39 r0 bottom
R51 "CRCW020133R2FNED" 0201_Silk 1340.12,1706.34 r270 bottom
R52 "CRCW02010000Z0ED" 0201_Silk 100.51,1106.03 r0 top
R53 "CRCW02010000Z0ED" 0201_Silk 603.39,1110.85 r0 top
R54 "CRCW040210K0FKED" 0402L 1518.82,486.5 r180 bottom
R55 "CRCW02010000Z0ED" 0201 1468.18,608.39 r0 bottom
R56 "CRCW02010000Z0ED" 0201 1589.36,569.98 r180 bottom
R57 "CRCW04020000Z0ED" 0402 1411.83,476.26 r180 bottom
R58 "CRCW02010000Z0ED" 0201_Silk 100.51,1064.82 r0 top
R59 "CRCW02010000Z0ED" 0201_Silk 118.65,763.99 r0 top
R60 "CRCW02010000Z0ED" 0201_Silk 118.65,725.13 r0 top
R61 "CRCW02010000Z0ED" 0201_Silk 118.65,686.13 r0 top
R62 "CRCW02010000Z0ED" 0201_Silk 135.17,600.8 r90 top
R63 "CRCW02010000Z0ED" 0201_Silk 178.77,600.8 r90 top
R64 "RC0201JR-07220RL" 0201 1432.93,1884.47 r90 top
R65 "CRCW040210K0FKED" 0402L 1380.92,1853.19 r270 top
R66 "RC0201JR-07510RL" 0201L 1620.43,278.61 r0 top
R67 "CRCW040210K0FKED" 0402L 1998.65,2344.51 r180 top
R68 "CRCW040261R9FKED" 0402L 244.56,1982.22 r180 top
R69 "CRCW02010000Z0ED" 0201_Silk 273.75,1845.83 r180 top
R70 "CRCW04021K00FKED" 0402L 2200.66,1241.02 r0 top
R71 "CRCW040210K0FKED" 0402L 652.72,1980.88 r180 top
R72 "CRCW040210K0FKED" 0402L 2266.65,1021.86 r270 bottom
R73 "CRCW0402100KFKED" 0402L 1363.83,2191.16 r270 top
R74 "CRCW0402100KFKED" 0402L 1156.68,2102.96 r270 top
R75 "CRCW040210K0FKED" 0402L 1310.15,2193.89 r270 bottom
R76 "CRCW040210K0FKED" 0402L 1592.79,1135.73 r90 top
R77 "CRCW02010000Z0ED" 0201_Silk 248.36,1975.69 r90 bottom
R78 "ERJ-2GE0R00X" 0402 368.95,2030.57 r180 top
R79 "CRCW040261R9FKED" 0402L 244.61,1935.61 r0 top
R80 "ERJ-2GE0R00X" 0402 301.11,1787.62 r0 top
R81 "CRCW040210K0FKED" 0402L 1203.42,2116.14 r270 bottom
R82 "CRCW040210K0FKED" 0402L 1203.42,2116.14 r270 top
R83 "CRCW02010000Z0ED" 0201_Silk 644.27,1578.25 r270 bottom
R84 "CRCW02010000Z0ED" 0201_Silk 593.44,931.82 r0 bottom
R85 "CRCW02010000Z0ED" 0201_Silk 552.76,1191.19 r270 bottom
R86 "CRCW04021K00FKED" 0402L 918.71,2486.17 r180 top
R87 "MCT06030Z0000ZP500" 0603 643.92,2260.51 r180 bottom
R88 "ERJ-2GE0R00X" 0402 593.75,2721.93 r180 top
R89 "CRCW04021K00FKED" 0402L 2057.77,2321.89 r90 top
R90 "CRCW040210K0FKED" 0402L 872.93,1855.82 r0 top
R91 "CRCW040210K0FKED" 0402L 1096.73,1857.39 r180 bottom
R92 "HCJ0603ZT0R00" FP-HCJ0603ZT0R00_0603-MFG 683.58,2761.17 r270 bottom
R93 "CRCW020133R2FNED" 0201_Silk 1258.82,2076.73 r90 top
R94 "CRCW040210K0FKED" 0402L 1751.5,1824.25 r90 bottom
R95 "CRCW0402100KFKED" 0402L 228.87,2096.89 r180 bottom
R96 "CRCW0402100KFKED" 0402L 195.06,1879.04 r90 bottom
R97 "CRCW040210K0FKED" 0402L 184.93,1387.83 r90 bottom
R98 "CRCW040210K0FKED" 0402L 164.81,1294.02 r180 bottom
R99 "CRCW0402100KFKED" 0402L 2362.98,2059.31 r90 bottom
R100 "CRCW02010000Z0ED" 0201_Silk 2099.4,2288.74 r270 bottom
R101 "CRCW040210K0FKED" 0402L 1808.6,1809.73 r180 bottom
R102 "CRCW040210K0FKED" 0402L 1480.36,1000.15 r180 top
R103 "CRCW040210K0FKED" 0402L 1860.96,1940.09 r180 bottom
R104 "CRCW040210K0FKED" 0402L 1709.02,1409.73 r180 bottom
R105 "CRCW040210K0FKED" 0402L 1867.14,1439.18 r0 bottom
R106 "CRCW040210K0FKED" 0402L 209.19,2199.63 r180 top
R107 "CRCW040210K0FKED" 0402L 264.04,2274.05 r180 top
R108 "CRCW02010000Z0ED" 0201 1606.16,1481.18 r180 bottom
R109 "CRCW02010000Z0ED" 0201 302.93,2089.59 r180 top
R110 "CRCW02010000Z0ED" 0201 1649.02,1542.83 r180 bottom
R111 "CRCW02010000Z0ED" 0201 228.87,2117.16 r270 top
R112 "CRCW040210K0FKED" 0402L 1856.78,1536.55 r180 bottom
R113 "CRCW040210K0FKED" 0402L 1812.67,1374.1 r270 bottom
R114 "CRCW040210K0FKED" 0402L 1867.14,1477.16 r180 bottom
R115 "CRCW040210K0FKED" 0402L 209.19,2166.36 r0 top
R116 "CRCW040210K0FKED" 0402L 209.19,2232.82 r0 top
R117 "CRCW040210K0FKED" 0402L 321.43,2283.53 r270 top
R118 "CRCW02010000Z0ED" 0201_Silk 248.36,1903.02 r270 bottom
R119 "RMCF0402FT68K0" FP-RMCF0402FT68K0_0402-MFG 173.4,2502.3 r90 bottom
R120 "CRCW0201100KFKED" 0201L 1541.9,988.57 r90 top
R121 "RMCF0402FT68K0" FP-RMCF0402FT68K0_0402-MFG 174.34,2395.53 r90 bottom
R122 "CRCW020133R2FNED" 0201_Silk 849.24,926.97 r0 top
R123 "CRCW040210K0FKED" 0402L 1310.79,286.13 r180 bottom
R124 "CRCW020133R2FNED" 0201_Silk 849.24,956.57 r0 top
R125 "CRCW020133R2FNED" 0201_Silk 849.24,1043.38 r0 top
R126 "CRCW020133R2FNED" 0201_Silk 681.65,1049.43 r90 bottom
R127 "ERJ-2GE0R00X" 0402 799.15,253.6 r90 bottom
R128 "ERJ-2GE0R00X" 0402 1327.79,1782.65 r90 top
R129 "MCT06030Z0000ZP500" 0603 1013.7,1276.86 r0 top
R130 "MCT06030Z0000ZP500" 0603 1519.94,1642.52 r270 top
R131 "CRCW040210K0FKED" 0402L 2017.19,2292.1 r90 top
R132 "MCT06030Z0000ZP500" 0603 218.54,2244.81 r180 bottom
R133 "CRCW02010000Z0ED" 0201_Silk 2337.72,1482.82 r270 bottom
R134 "WSL1206R0200FEB" FP-WSL1206R0200FEB_1206-MFG 421.05,2823.99 r0 bottom
R135 "CRCW040210K0FKED" 0402L 452.2,3025.66 r0 top
R136 "CRCW040210K0FKED" 0402L 348.19,3081.58 r180 bottom
R137 "CRCW02010000Z0ED" 0201 532.63,3073.14 r270 bottom
R138 "CRCW040210K0FKED" 0402L 1369.02,194.08 r270 bottom
R139 "CRCW02010000Z0ED" 0201 503.6,3127.45 r0 bottom
R140 "CRCW02010000Z0ED" 0201_Silk 2350.08,1993.71 r0 bottom
R141 "RC0201JR-07510RL" 0201L 1711.5,114.16 r90 top
R142 "CRCW040210K0FKED" 0402L 431.44,3128.96 r0 bottom
R143 "CRCW02010000Z0ED" 0201_Silk 1949.41,1804.6 r270 bottom
R144 "CRCW02010000Z0ED" 0201_Silk 2337.72,1781.04 r270 bottom
R145 "CRCW02010000Z0ED" 0201_Silk 2337.72,1679.83 r270 bottom
R146 "CRCW02010000Z0ED" 0201_Silk 247.61,1581.92 r90 bottom
R147 "CRCW02010000Z0ED" 0201_Silk 1957.66,1578.25 r90 bottom
R148 "CRCW040210K0FKED" 0402L 452.2,2987.41 r180 top
R149 "CRCW02010000Z0ED" 0201_Silk 228.01,1491.41 r0 bottom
